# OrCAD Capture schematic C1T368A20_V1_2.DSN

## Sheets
1 EMMC: size A4; title: Telink; rev: V1.2; note: C1T368A20
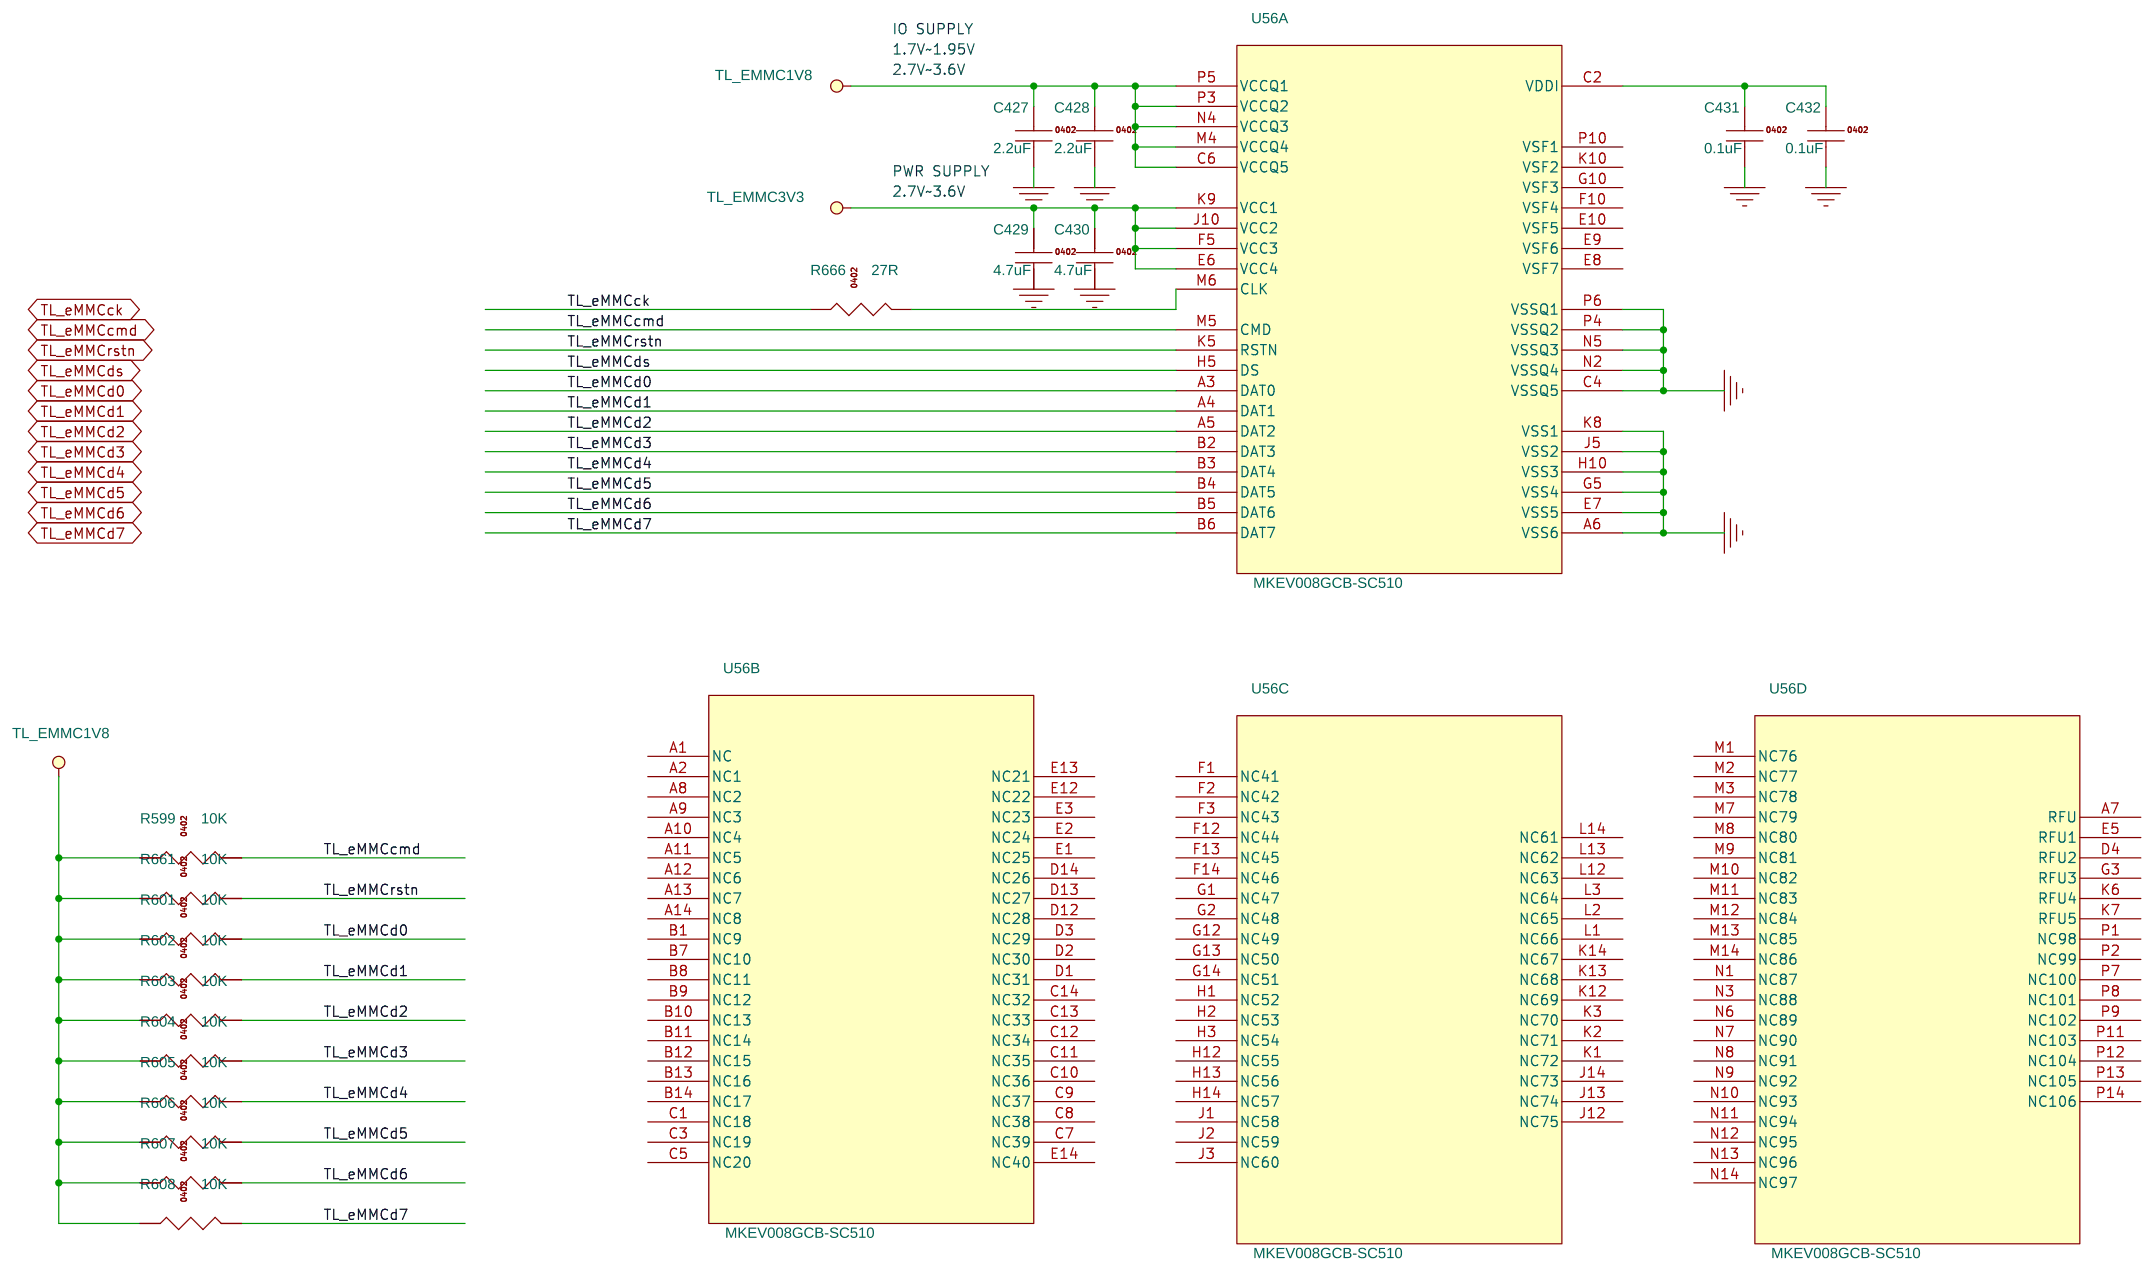
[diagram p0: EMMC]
2 001_Log
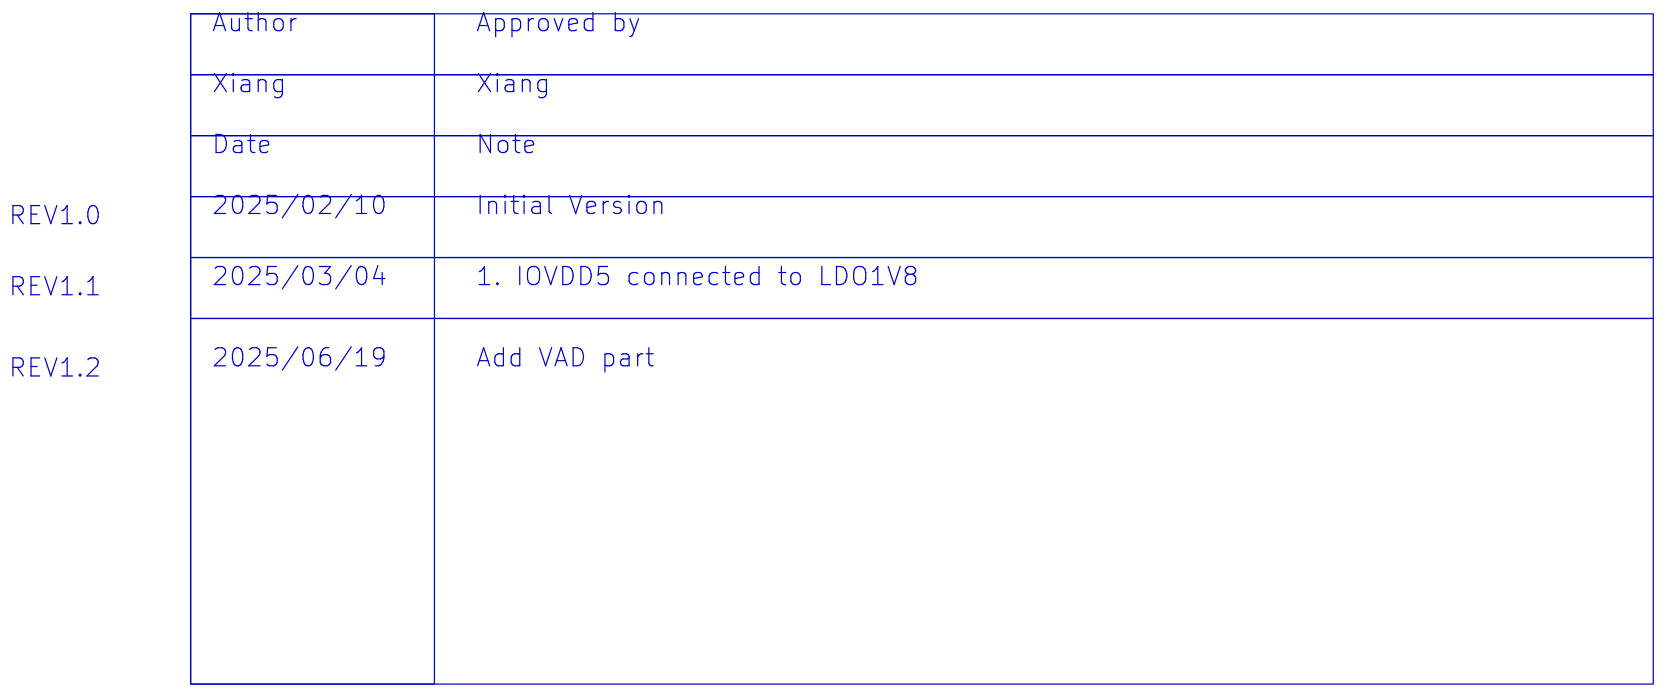
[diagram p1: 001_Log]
3 002_STR
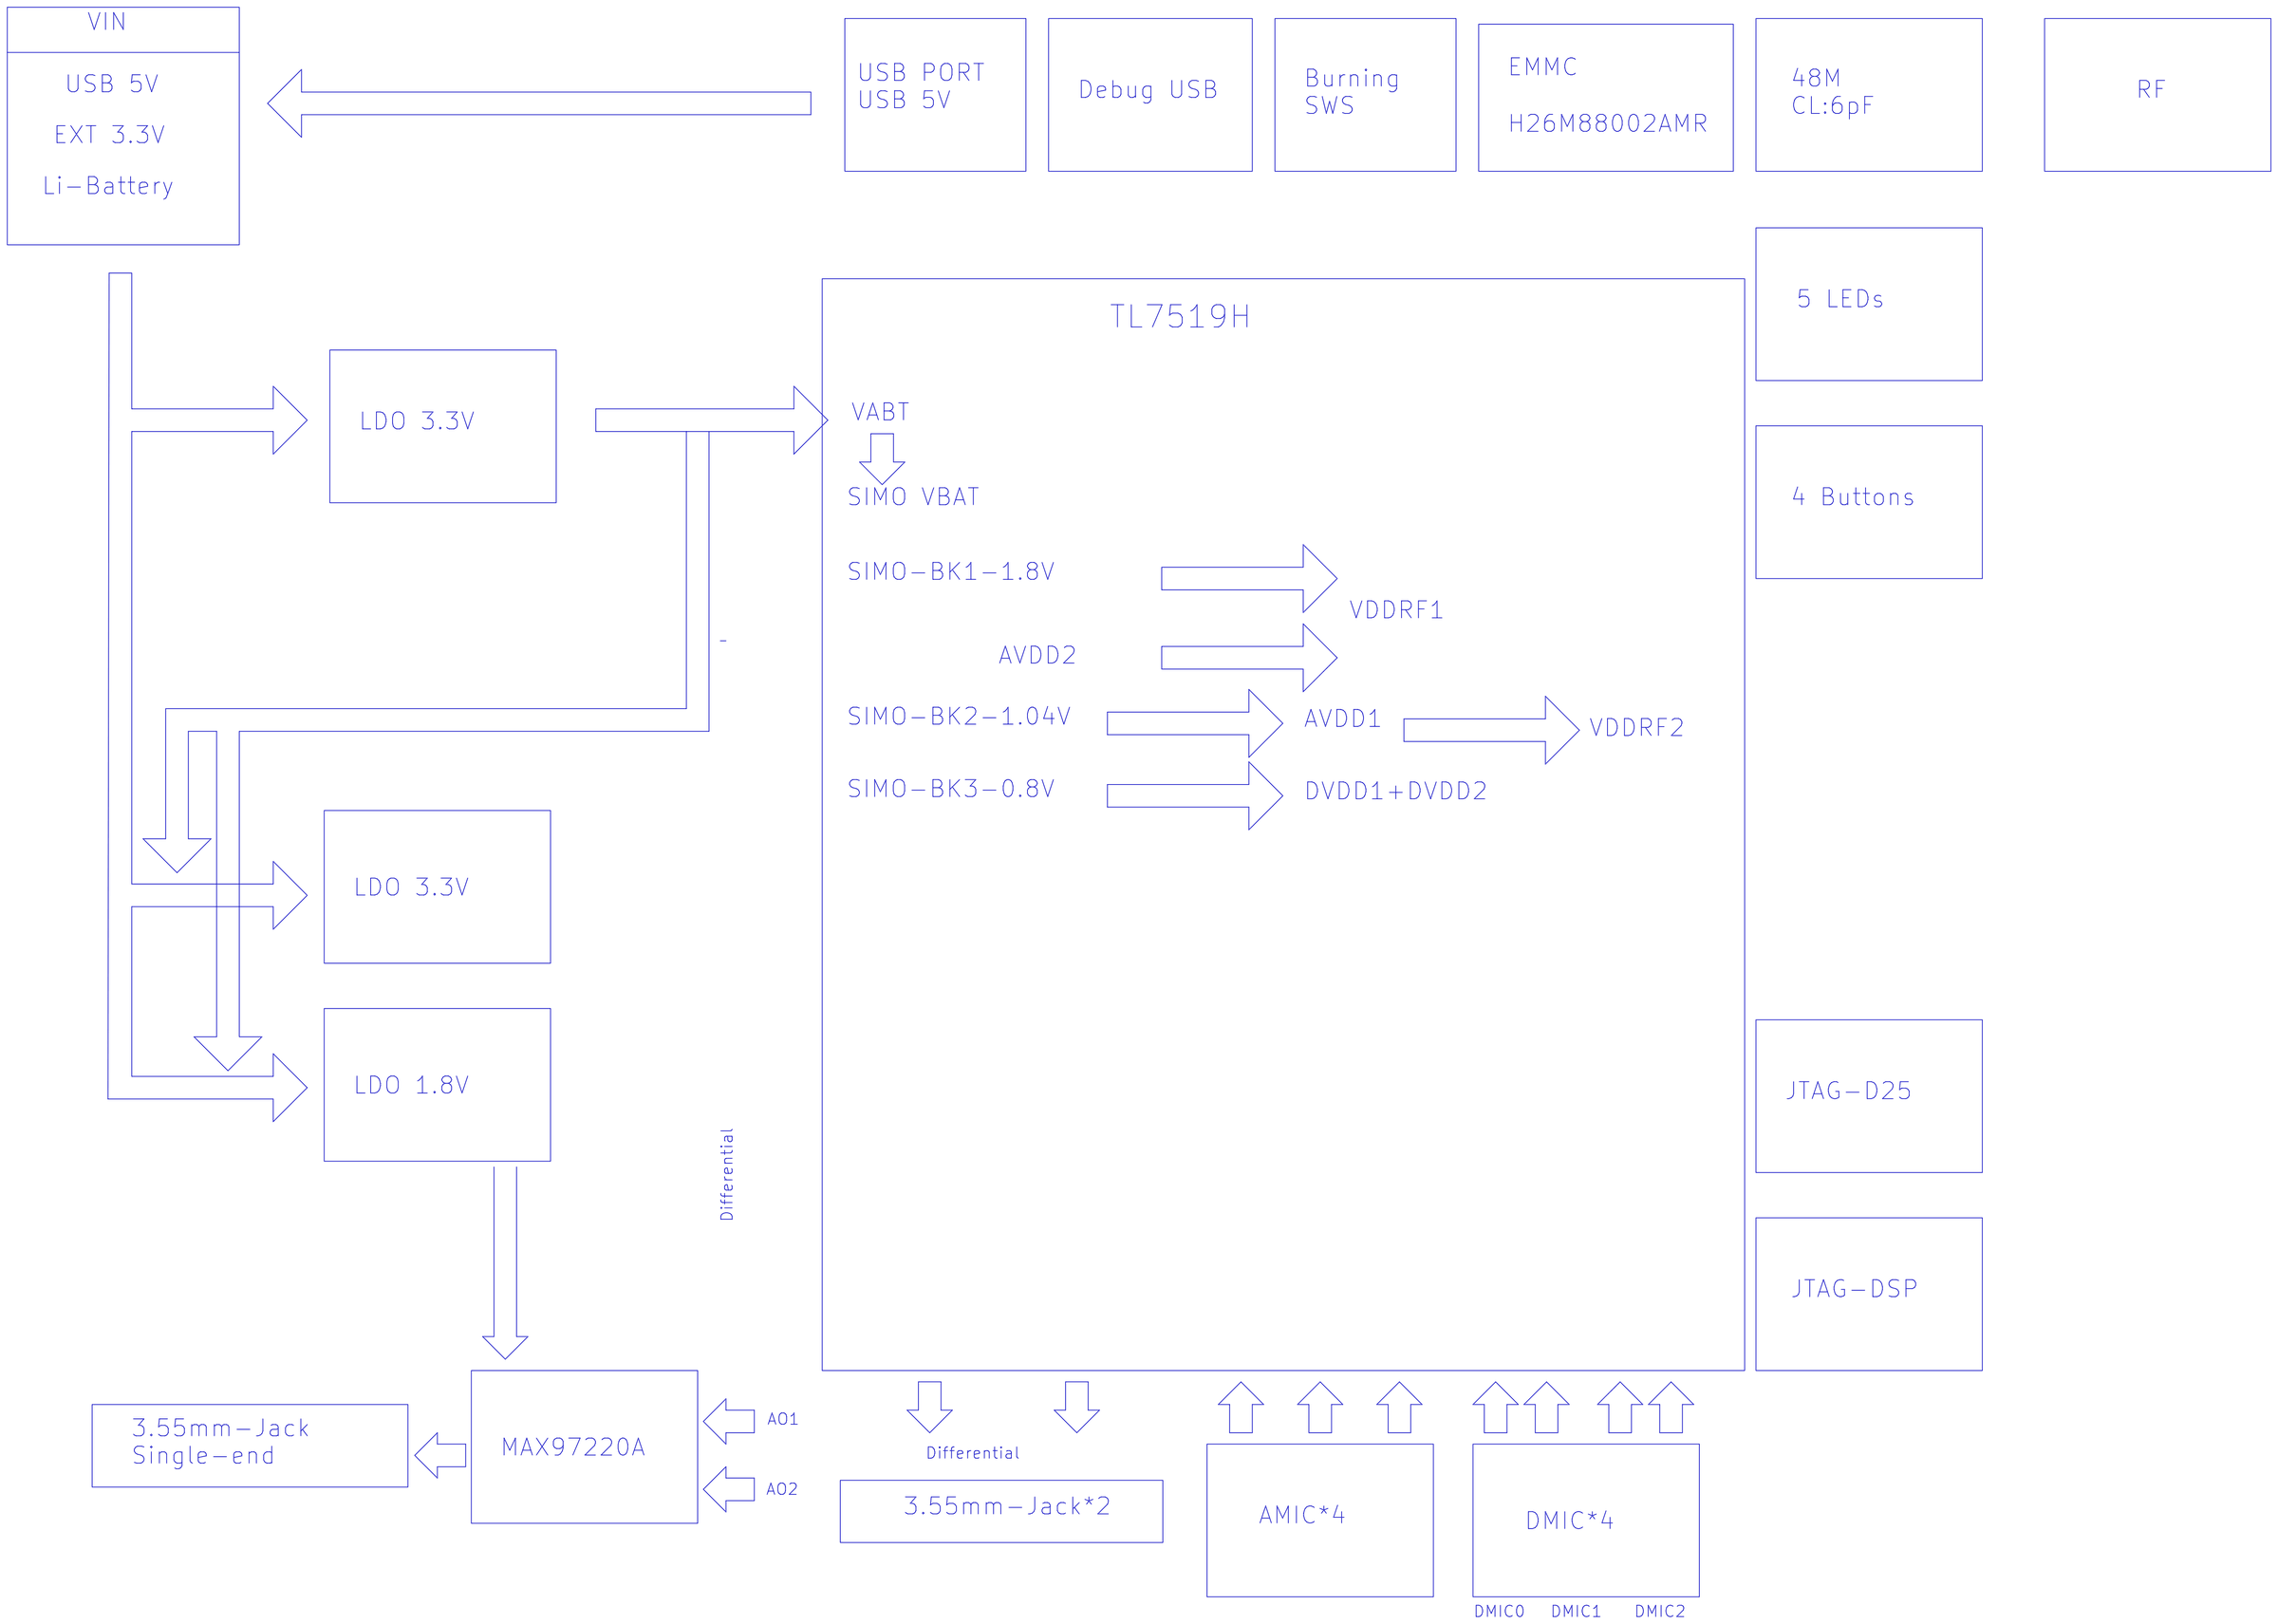
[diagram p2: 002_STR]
4 003_MAIN: size A4
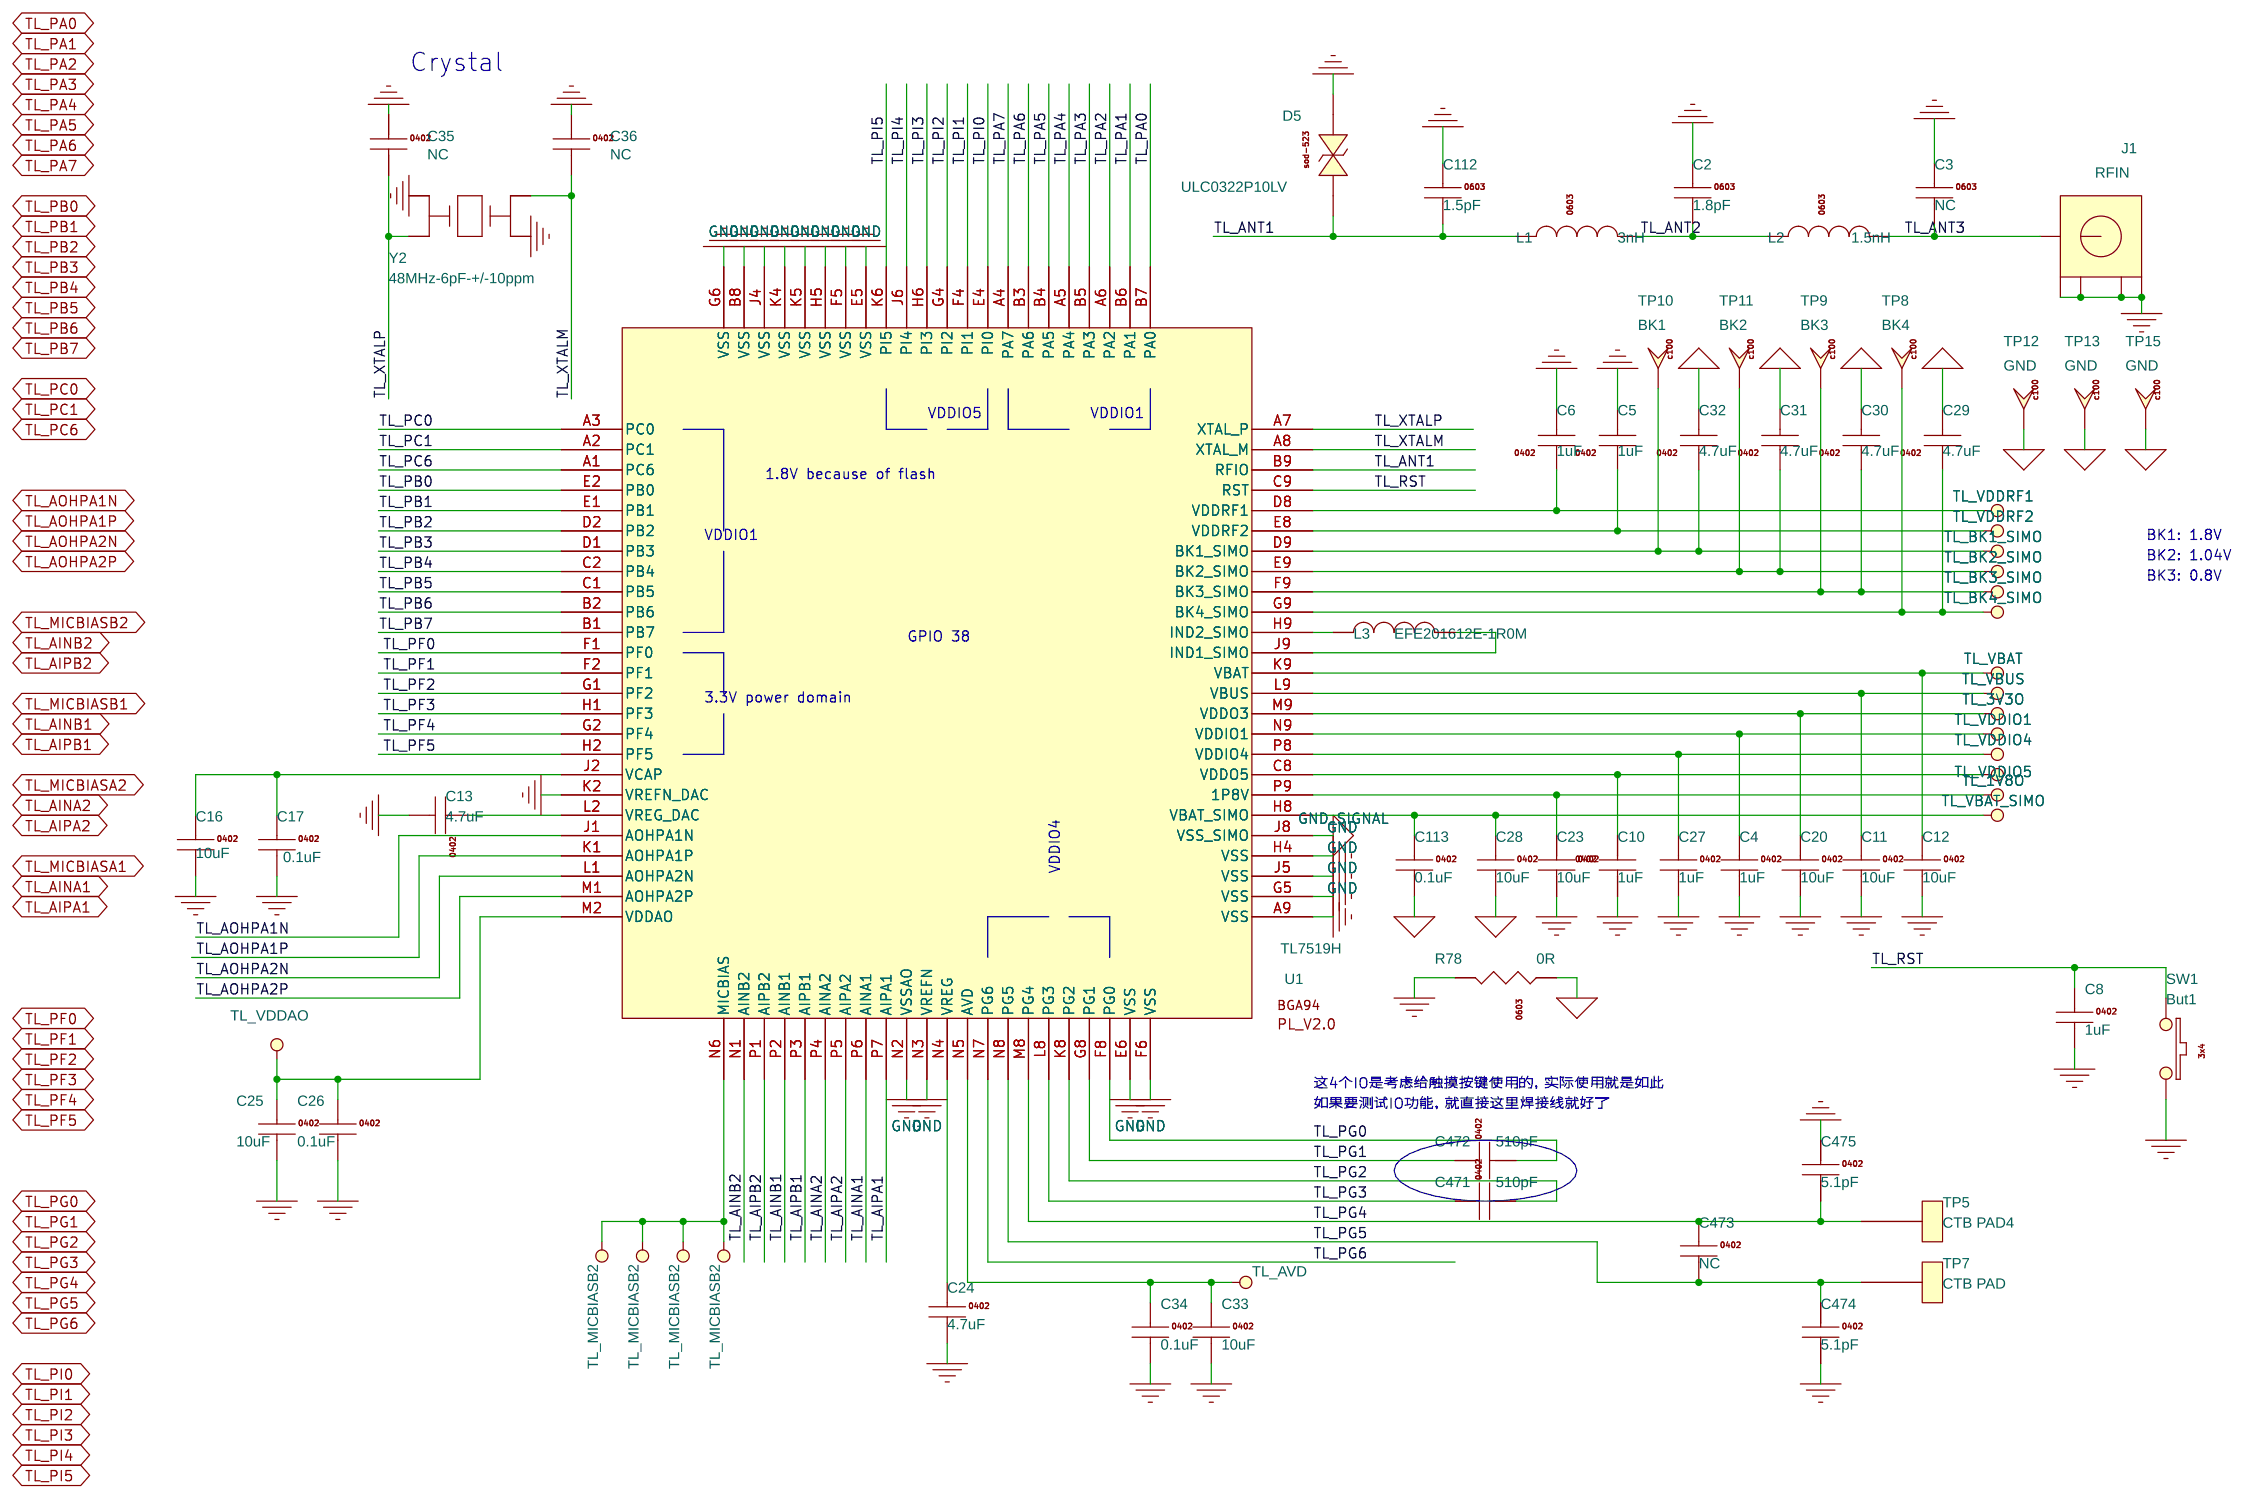
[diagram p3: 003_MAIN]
5 004_Interface: size A4
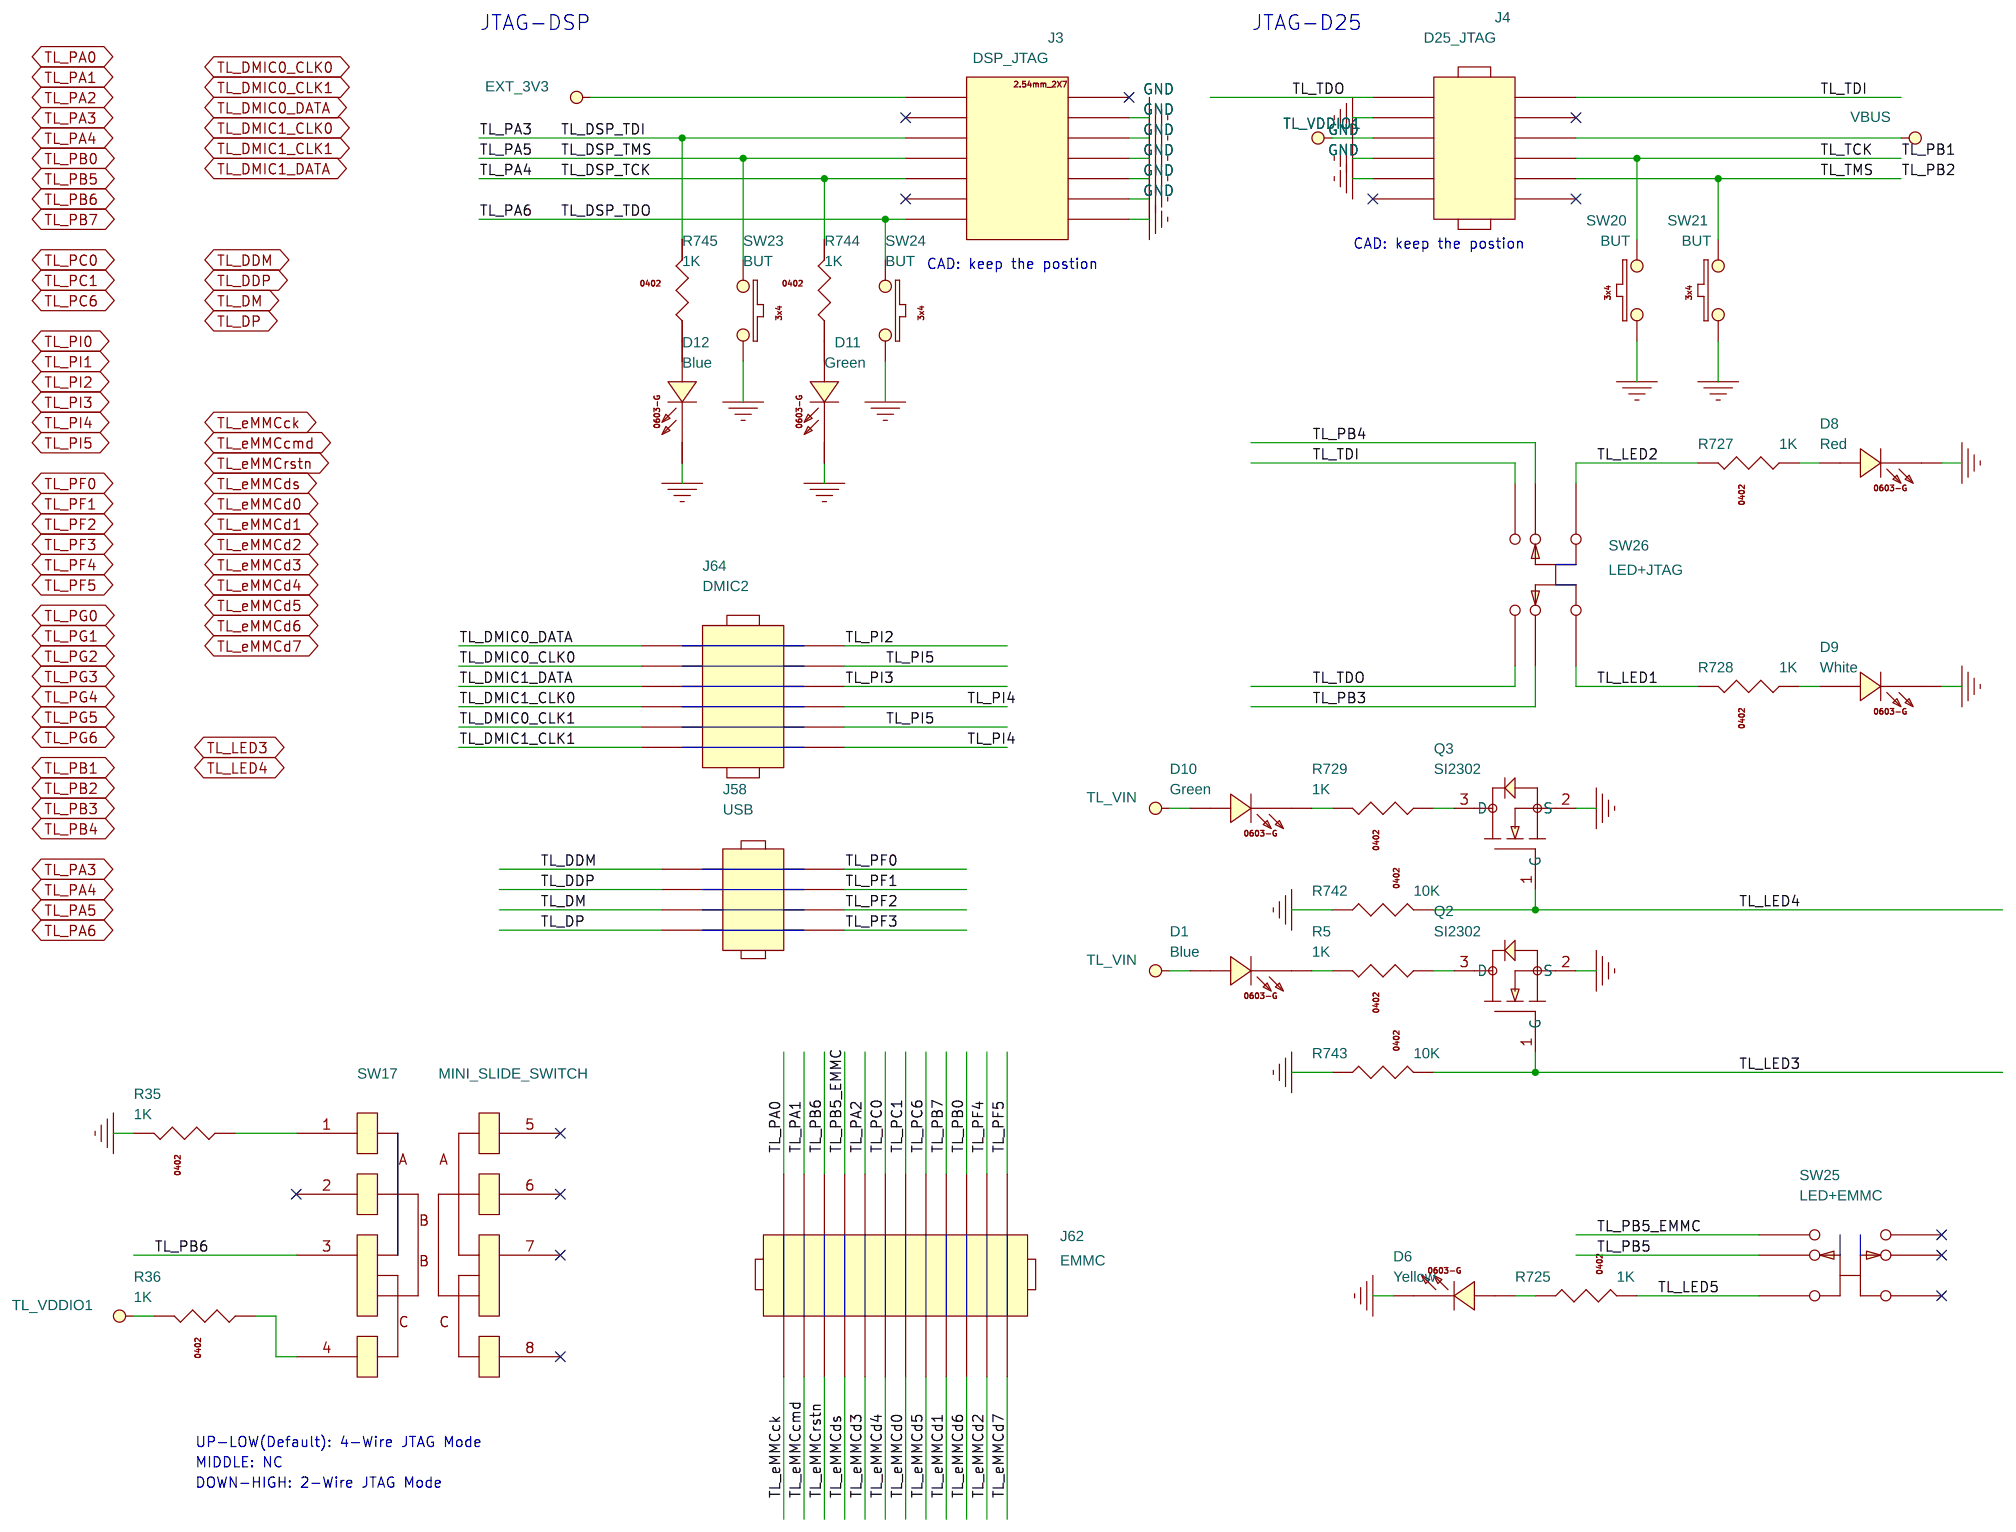
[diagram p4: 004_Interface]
6 005_AMIC: size A3
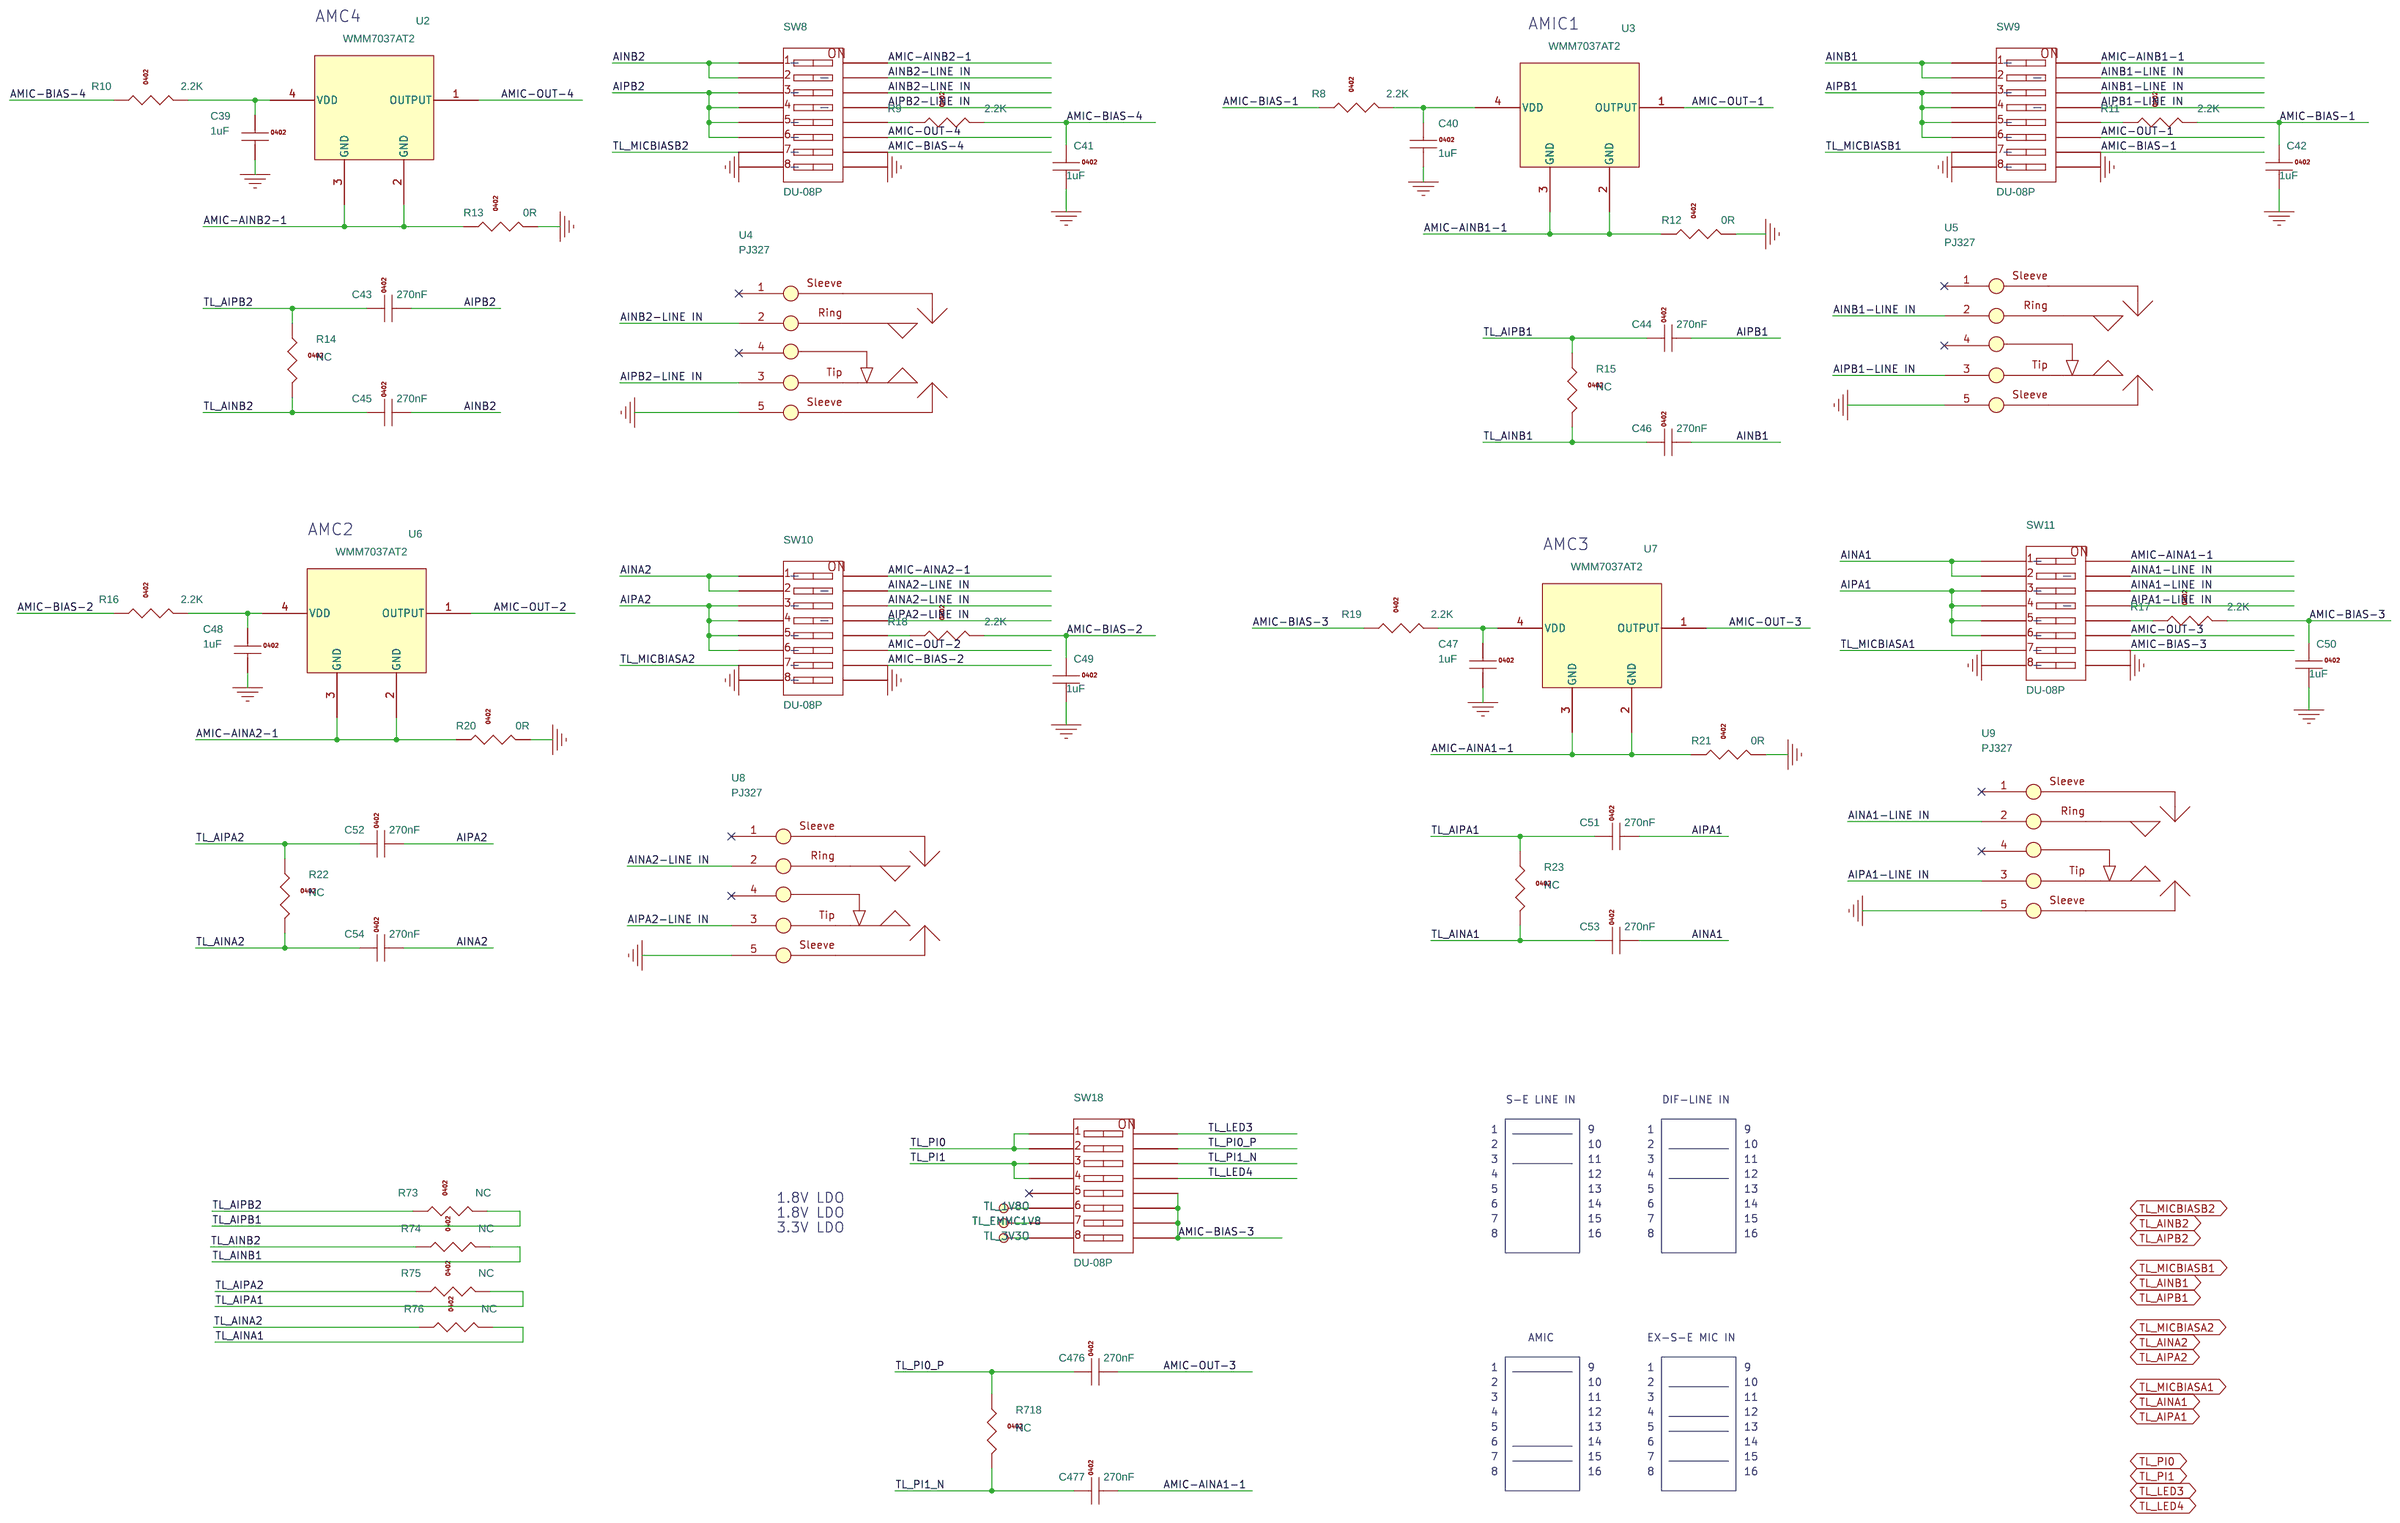
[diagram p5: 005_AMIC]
7 006_DMIC: size A4
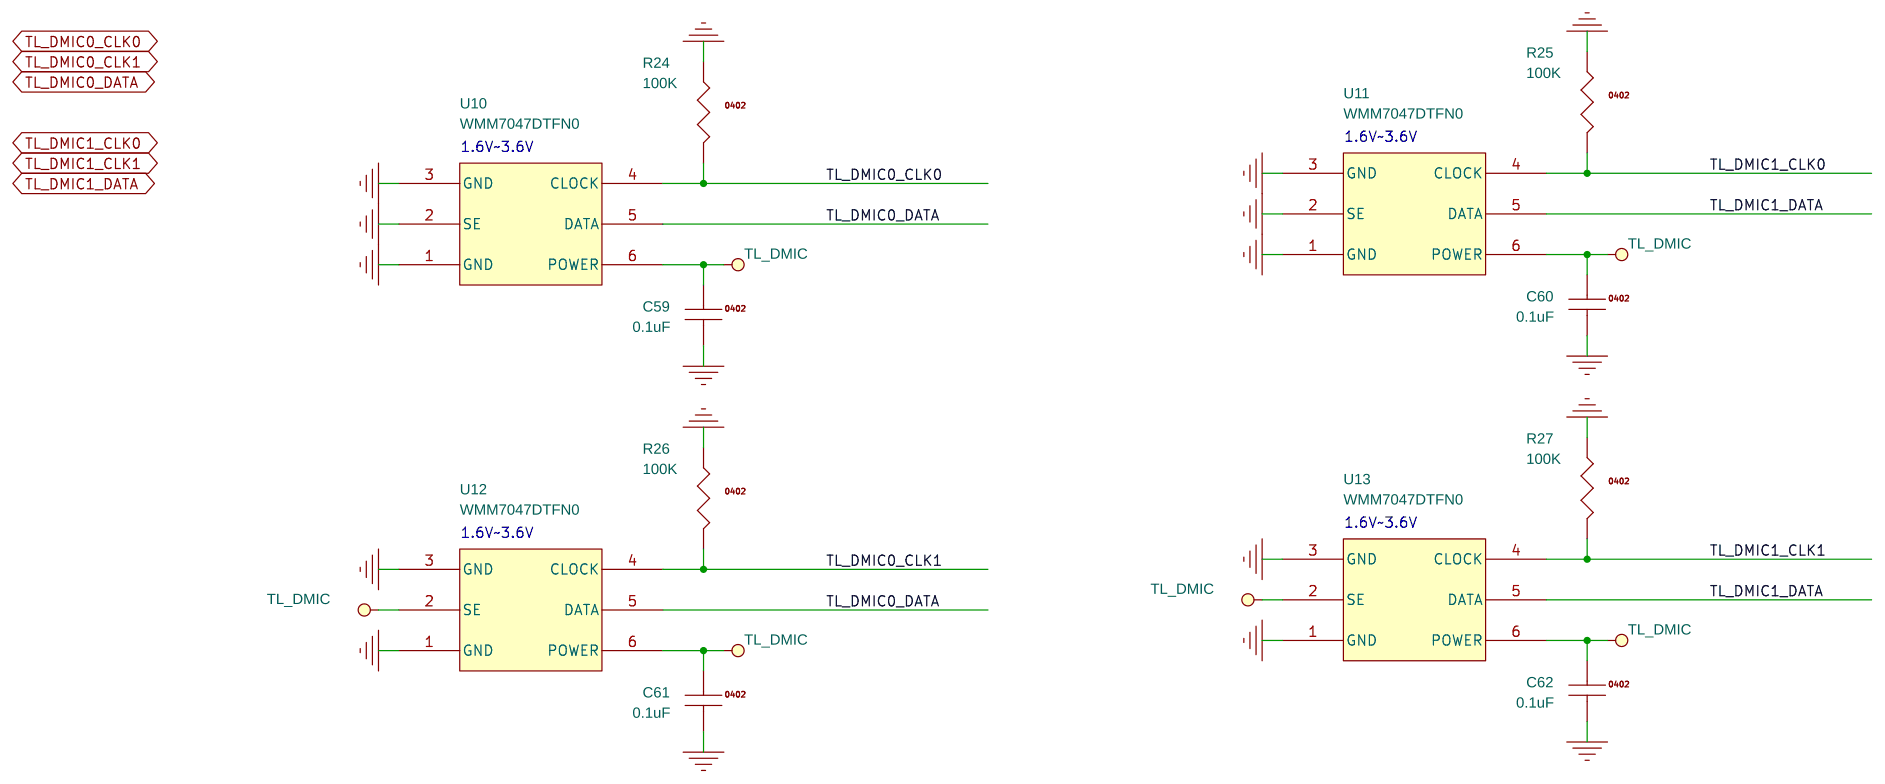
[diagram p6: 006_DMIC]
8 007_DAC Output: size A4
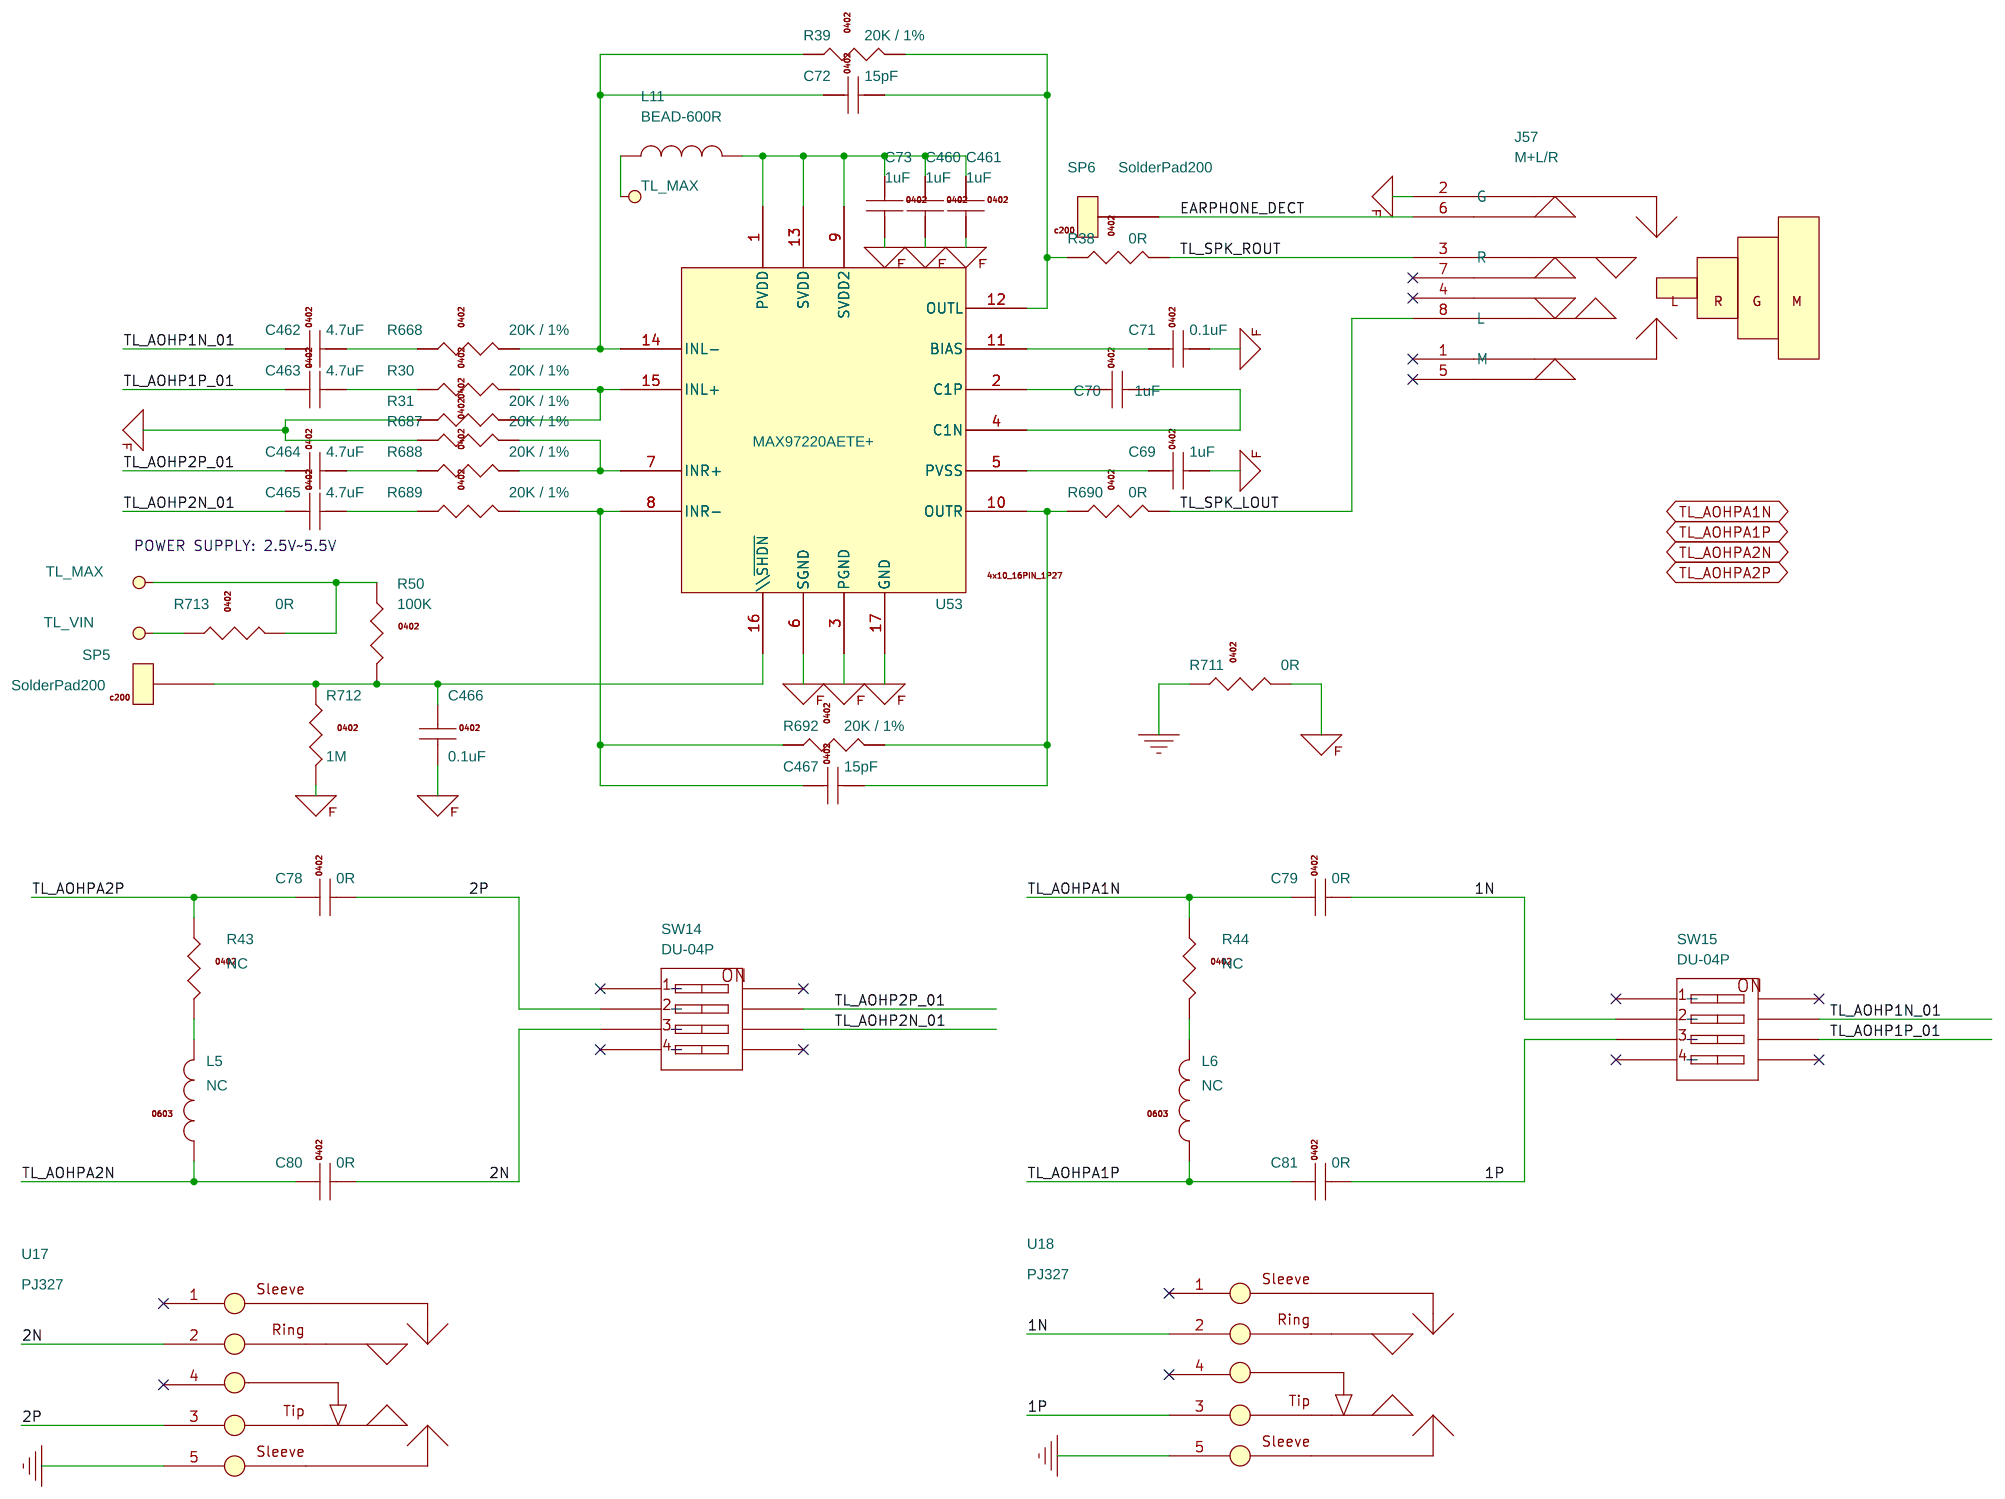
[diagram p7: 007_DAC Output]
9 009_PWR: size A4
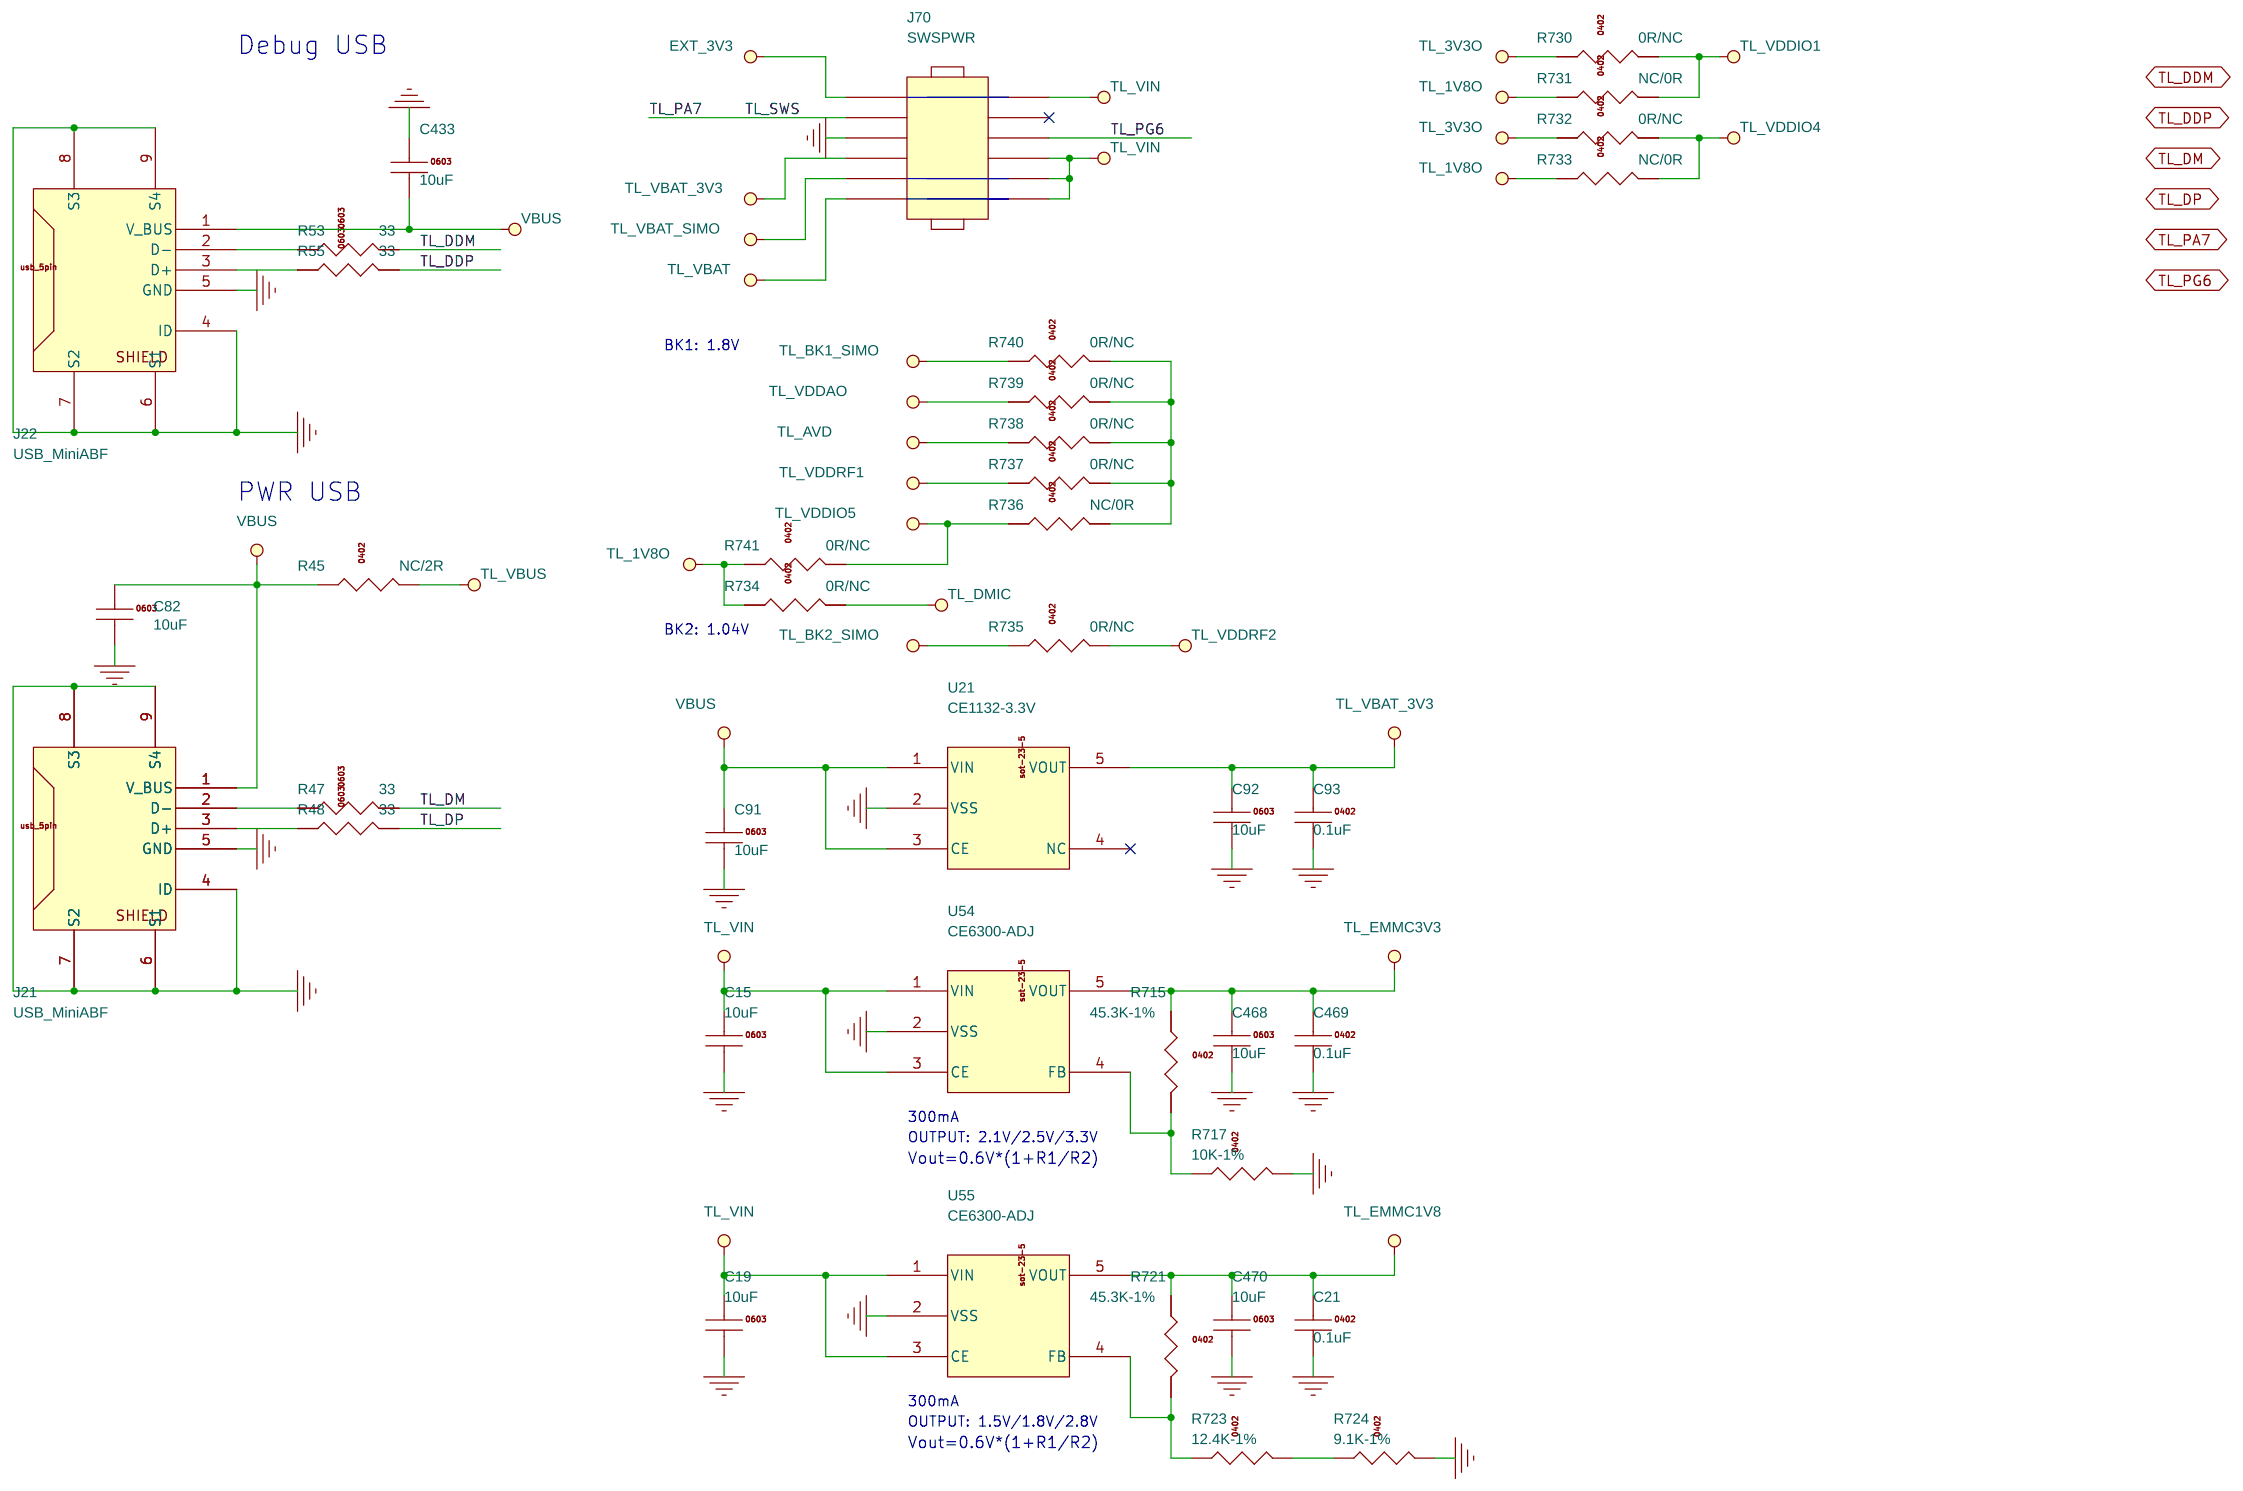
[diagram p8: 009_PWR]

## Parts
sheet 003_MAIN
C2  1.8pF  [0201]
C3  NC  [0201]
C4  1uF  [0402]
C5  1uF  [0402]
C6  1uF  [0402]
C8  1uF  [0402]
C10  1uF  [0402]
C11  10uF  [0402]
C12  10uF  [0402]
C13  4.7uF  [0402]
C16  10uF  [0402]
C17  0.1uF  [0402]
C20  10uF  [0402]
C23  10uF  [0402]
C24  4.7uF  [0402]
C25  10uF  [0402]
C26  0.1uF  [0402]
C27  1uF  [0402]
C28  10uF  [0402]
C29  4.7uF  [0402]
C30  4.7uF  [0402]
C31  4.7uF  [0402]
C32  4.7uF  [0402]
C33  10uF  [0402]
C34  0.1uF  [0402]
C35  NC  [0402]
C36  NC  [0402]
C112  1.5pF  [0201]
C113  0.1uF  [0402]
C471  510pF  [0402]
C472  510pF  [0402]
C473  NC  [0402]
C474  5.1pF  [0402]
C475  5.1pF  [0402]
D5  ULC0322P10LV  [0201]
J1  RFIN  [SMA-H]
L1  3nH  [0201]
L2  1.5nH  [0201]
L3  EFE201612E-1R0M  [1008L]
R78  0R  [0402]
SW1  But1  [butsmd2px4_00y3_00_nh]
TP5  CTB PAD4  [tp12mm]
TP7  CTB PAD  [tp12mm]
TP8  BK4  [TP100]
TP9  BK3  [TP100]
TP10  BK1  [TP100]
TP11  BK2  [TP100]
TP12  GND  [TP100]
TP13  GND  [TP100]
TP15  GND  [TP100]
U1  TL7519H  [bga_4x6_94pin_0p4]
Y2  48MHz-6pF-+/-10ppm  [OSCCC250X320X110]
sheet 004_Interface
D1  Blue  [0603-LED]
D6  Yellow  [0603-LED]
D8  Red  [0603-LED]
D9  White  [0603-LED]
D10  Green  [0603-LED]
D11  Green  [0603-LED]
D12  Blue  [0603-LED]
J3  DSP_JTAG  [smd254m-2x7_rx1_30y2_40]
J4  D25_JTAG  [smd254m-2x6_rx1_30y2_40]
J58  USB  [smd254m-2x4_rx1_30y2_40]
J62  EMMC  [smd254m-2x12_rx1_30y2_40]
J64  DMIC2  [smd254m-2x6_rx1_30y2_40]
Q2  SI2302  [mos_sot-23]
Q3  SI2302  [mos_sot-23]
R5  1K  [0402]
R35  1K  [0402]
R36  1K  [0402]
R725  1K  [0402]
R727  1K  [0402]
R728  1K  [0402]
R729  1K  [0402]
R742  10K  [0402]
R743  10K  [0402]
R744  1K  [0402]
R745  1K  [0402]
SW17  MINI_SLIDE_SWITCH  [SW-SMD-8PIN-12P95X3P5-2]
SW20  BUT  [butsmd2px4_00y3_00_nh]
SW21  BUT  [butsmd2px4_00y3_00_nh]
SW23  BUT  [butsmd2px4_00y3_00_nh]
SW24  BUT  [butsmd2px4_00y3_00_nh]
SW25  LED+EMMC  [SW-SMD-6PIN-9P1X3P5-2P5]
SW26  LED+JTAG  [SW-SMD-6PIN-9P1X3P5-2P5]
sheet 005_AMIC
C39  1uF  [0402]
C40  1uF  [0402]
C41  1uF  [0402]
C42  1uF  [0402]
C43  270nF  [0402]
C44  270nF  [0402]
C45  270nF  [0402]
C46  270nF  [0402]
C47  1uF  [0402]
C48  1uF  [0402]
C49  1uF  [0402]
C50  1uF  [0402]
C51  270nF  [0402]
C52  270nF  [0402]
C53  270nF  [0402]
C54  270nF  [0402]
C476  270nF  [0402]
C477  270nF  [0402]
R8  2.2K  [0402]
R9  2.2K  [0402]
R10  2.2K  [0402]
R11  2.2K  [0402]
R12  0R  [0402]
R13  0R  [0402]
R14  NC  [0402]
R15  NC  [0402]
R16  2.2K  [0402]
R17  2.2K  [0402]
R18  2.2K  [0402]
R19  2.2K  [0402]
R20  0R  [0402]
R21  0R  [0402]
R22  NC  [0402]
R23  NC  [0402]
R73  NC  [0402]
R74  NC  [0402]
R75  NC  [0402]
R76  NC  [0402]
R718  NC  [0402]
SW8  DU-08P  [EHS-JH_1p27_8x2]
SW9  DU-08P  [EHS-JH_1p27_8x2]
SW10  DU-08P  [EHS-JH_1p27_8x2]
SW11  DU-08P  [EHS-JH_1p27_8x2]
SW18  DU-08P  [EHS-JH_1p27_8x2]
U2  WMM7037AT2  [ga_bfa423_a83]
U3  WMM7037AT2  [ga_bfa423_a83]
U4  PJ327  [PJ-327]
U5  PJ327  [PJ-327]
U6  WMM7037AT2  [ga_bfa423_a83]
U7  WMM7037AT2  [ga_bfa423_a83]
U8  PJ327  [PJ-327]
U9  PJ327  [PJ-327]
sheet 006_DMIC
C59  0.1uF  [0402]
C60  0.1uF  [0402]
C61  0.1uF  [0402]
C62  0.1uF  [0402]
R24  100K  [0402]
R25  100K  [0402]
R26  100K  [0402]
R27  100K  [0402]
U10  WMM7047DTFN0  [DMIC_SPM0423HM4H-WB]
U11  WMM7047DTFN0  [DMIC_SPM0423HM4H-WB]
U12  WMM7047DTFN0  [DMIC_SPM0423HM4H-WB]
U13  WMM7047DTFN0  [DMIC_SPM0423HM4H-WB]
sheet 007_DAC Output
C69  1uF  [0402]
C70  1uF  [0402]
C71  0.1uF  [0402]
C72  15pF  [0402]
C73  1uF  [0402]
C78  0R  [0402]
C79  0R  [0402]
C80  0R  [0402]
C81  0R  [0402]
C460  1uF  [0402]
C461  1uF  [0402]
C462  4.7uF  [0402]
C463  4.7uF  [0402]
C464  4.7uF  [0402]
C465  4.7uF  [0402]
C466  0.1uF  [0402]
C467  15pF  [0402]
J57  M+L/R  [PJ-382-8P]
L5  NC  [1008L]
L6  NC  [1008L]
L11  BEAD-600R  [0603L]
R30  20K / 1%  [0402]
R31  20K / 1%  [0402]
R38  0R  [0402]
R39  20K / 1%  [0402]
R43  NC  [0402]
R44  NC  [0402]
R50  100K  [0402]
R668  20K / 1%  [0402]
R687  20K / 1%  [0402]
R688  20K / 1%  [0402]
R689  20K / 1%  [0402]
R690  0R  [0402]
R692  20K / 1%  [0402]
R711  0R  [0402]
R712  1M  [0402]
R713  0R  [0402]
SP5  SolderPad200  [TP200]
SP6  SolderPad200  [TP200]
SW14  DU-04P  [EHS-JH_1p27_4x2]
SW15  DU-04P  [EHS-JH_1p27_4x2]
U17  PJ327  [PJ-327]
U18  PJ327  [PJ-327]
U53  MAX97220AETE+  [qfn_3x3_16pin_0p5_1p70x1p70]
sheet 009_PWR
C15  10uF  [0603C]
C19  10uF  [0603C]
C21  0.1uF  [0402]
C82  10uF  [0603C]
C91  10uF  [0603C]
C92  10uF  [0603C]
C93  0.1uF  [0402]
C433  10uF  [0603C]
C468  10uF  [0603C]
C469  0.1uF  [0402]
C470  10uF  [0603C]
J21  USB_MiniABF  [USB-MINI-F5]
J22  USB_MiniABF  [USB-MINI-F5]
J70  SWSPWR  [smd254m-2x6_rx1_30y2_40]
R45  NC/2R  [0402]
R47  33  [0402R]
R48  33  [0402R]
R53  33  [0402R]
R55  33  [0402R]
R715  45.3K-1%  [0402]
R717  10K-1%  [0402]
R721  45.3K-1%  [0402]
R723  12.4K-1%  [0402]
R724  9.1K-1%  [0402]
R730  0R/NC  [0402]
R731  NC/0R  [0402]
R732  0R/NC  [0402]
R733  NC/0R  [0402]
R734  0R/NC  [0402]
R735  0R/NC  [0402]
R736  NC/0R  [0402]
R737  0R/NC  [0402]
R738  0R/NC  [0402]
R739  0R/NC  [0402]
R740  0R/NC  [0402]
R741  0R/NC  [0402]
U21  CE1132-3.3V  [sot-23-5]
U54  CE6300-ADJ  [sot-23-5]
U55  CE6300-ADJ  [sot-23-5]
sheet EMMC
C427  2.2uF  [0402]
C428  2.2uF  [0402]
C429  4.7uF  [0402]
C430  4.7uF  [0402]
C431  0.1uF  [0402]
C432  0.1uF  [0402]
R599  10K  [0402]
R601  10K  [0402]
R602  10K  [0402]
R603  10K  [0402]
R604  10K  [0402]
R605  10K  [0402]
R606  10K  [0402]
R607  10K  [0402]
R608  10K  [0402]
R661  10K  [0402]
R666  27R  [0402]
U56  MKEV008GCB-SC510  [FBGA153]  (sections A,B,C,D)

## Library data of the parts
C2 C3 C112 = C1608_NC
C4-C6 C8 C10-C13 C16 C17 C20 C21 C23-C34 C39-C54 C59-C62 C69-C73 C93 C113 C427-C432 C460-C467 C469 C471-C477 = C1005X5R1C104K
C35 C36 = C1005_NC
D5 = ESD5B5_0.0ST1G
J1 = SMA_JACK_2: PART: RF
L1 L2 L5 L6 = MLK1608_000R
L3 L11 = IND
R78 = RS0603K102JT
SW1 SW20 SW21 SW23 SW24 = SW2PIN_3x4
TP5 TP7 = TEST_POINT
TP8-TP13 TP15 = TestPad100
U1 = TL7519H-BGA94
Y2 = CRYSTAL4_SM_0
D1 D6 D8-D12 = 0603D_Green
J3 = CON_0.54mm_2x7
J4 J64 J70 = HEADER_6X2
J58 = HEADER_4X2
J62 = HEADER_12X2
Q2 Q3 = NMOS_SI2302
R5 R715 R717 R721 R723-R725 R727-R729 R744 R745 = RS0402K102JT
R35 R36 R742 R743 = RS0402K103JT
SW17 = MINI_SLIDE_SWITCH
SW25 SW26 = SW_SL_DPDT
R8-R27 R30 R31 R38 R39 R43-R45 R50 R73-R76 R668 R687-R690 R692 R711-R713 R718 R730-R741 = RS0402K104JT
SW8-SW11 SW18 = EHS-JH-108
U2 U3 U6 U7 = MULPS4CX-RM5_0
U4 U5 U8 U9 U17 U18 = PJ327
U10-U13 = LD1117_SO_0
C78-C81 = C1005X5R1C105K
J57 = PJ327_2
SP5 SP6 = SolderPad200
SW14 SW15 = EHS-JH-104
U53 = TLSR8368EP16_1
C15 C19 C82 C91 C92 C433 C468 C470 = C1608X5R0J106M
J21 J22 = USB_MiniABF_5pin
R47 R48 R53 R55 = RS0603K330JT
U21 = XC6219_5.3V_SOT-23-5
U54 U55 = XC6219_1.3V_SOT-23-5
R599 R601-R608 R661 R666 = RS0402K330JT
U56 = H26M88002AMR

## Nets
GND: C2.1 C3.1 C4.2 C5.2 C6.2 C8.2 C10.2 C11.2 C12.2 C13.2 C15.2 C16.2 C17.2 C19.2 C20.2 C21.2 C23.2 C24.2 C25.2 C26.2 C27.2 C33.2 C34.2 C35.1 C36.1 C39.2 C40.2 C41.2 C42.2 C47.2 C48.2 C49.2 C50.2 C59.2 C60.2 C61.2 C62.2 C82.2 C91.2 C92.2 C93.2 C112.1 C427.2 C428.2 C429.2 C430.2 C431.2 C432.2 C433.1 C468.2 C469.2 C470.2 C474.2 C475.1 D5.2 D6.C(CATHODE) D8.C(CATHODE) D9.C(CATHODE) D11.C(CATHODE) D12.C(CATHODE) J1.2 J1.3 J1.4 J1.5 J3.3 J3.5 J3.7 J3.9 J3.11 J3.13 J4.3 J4.5 J4.9 J21.4(ID) J21.5(GND) J21.6(S1) J21.7(S2) J21.8(S3) J21.9(S4) J22.4(ID) J22.5(GND) J22.6(S1) J22.7(S2) J22.8(S3) J22.9(S4) J70.6 Q2.2(S) Q3.2(S) R12.2 R13.2 R20.2 R21.2 R24.1 R25.1 R26.1 R27.1 R35.1 R78.2 R711.1 R717.2 R724.2 R742.2 R743.2 SW1.2 SW8.8 SW8.16 SW9.8 SW9.16 SW10.8 SW10.16 SW11.8 SW11.16 SW20.2 SW21.2 SW23.2 SW24.2 U1.A9(VSS) U1.B8(VSS) U1.E5(VSS) U1.E6(VSS) U1.F5(VSS) U1.F6(VSS) U1.G5(VSS) U1.G6(VSS) U1.H4(VSS) U1.H5(VSS) U1.J4(VSS) U1.J5(VSS) U1.K2(VREFN_DAC) U1.K4(VSS) U1.K5(VSS) U1.N2(VSSAO) U1.N3(VREFN) U4.5 U5.5 U8.5 U9.5 U10.1(GND) U10.2(SE) U10.3(GND) U11.1(GND) U11.2(SE) U11.3(GND) U12.1(GND) U12.3(GND) U13.1(GND) U13.3(GND) U17.5 U18.5 U21.2(VSS) U54.2(VSS) U55.2(VSS) U56.A6(VSS6) U56.C4(VSSQ5) U56.E7(VSS5) U56.G5(VSS4) U56.H10(VSS3) U56.J5(VSS2) U56.K8(VSS1) U56.N2(VSSQ4) U56.N5(VSSQ3) U56.P4(VSSQ2) U56.P6(VSSQ1) Y2.2 Y2.4
GND_FIELD SIGNAL: C69.2 C71.2 C73.2 C460.2 C461.2 C466.2 J57.2(G) R31.1 R687.1 R711.2 R712.2 U53.3(PGND) U53.6(SGND) U53.17(GND)
GND_SIGNAL: C28.2 C29.2 C30.2 C31.2 C32.2 C113.2 R78.1 TP12.1(TP) TP13.1(TP) TP15.1(TP) U1.J8(VSS_SIMO)
VBUS: C82.1 C91.1 C433.2 J4.8 J21.1(V_BUS) J22.1(V_BUS) R45.1 U21.1(VIN) U21.3(CE)
1N: C79.2 SW15.2 U18.2
1P: C81.2 SW15.3 U18.3
2N: C80.2 SW14.3 U17.2
2P: C78.2 SW14.2 U17.3
AINA1: C53.2 SW11.1 SW11.2
AINA1-LINE IN: SW11.10 SW11.11 U9.2
AINA2: C54.2 SW10.1 SW10.2
AINA2-LINE IN: SW10.10 SW10.11 U8.2
AINB1: C46.2 SW9.1 SW9.2
AINB1-LINE IN: SW9.10 SW9.11 U5.2
AINB2: C45.2 SW8.1 SW8.2
AINB2-LINE IN: SW8.10 SW8.11 U4.2
AIPA1: C51.2 SW11.3 SW11.4 SW11.5 SW11.6
AIPA1-LINE IN: SW11.12 U9.3
AIPA2: C52.2 SW10.3 SW10.4 SW10.5 SW10.6
AIPA2-LINE IN: SW10.12 U8.3
AIPB1: C44.2 SW9.3 SW9.4 SW9.5 SW9.6
AIPB1-LINE IN: SW9.12 U5.3
AIPB2: C43.2 SW8.3 SW8.4 SW8.5 SW8.6
AIPB2-LINE IN: SW8.12 U4.3
AMIC-AINA1-1: C477.2 R21.1 SW11.9 U7.2(GND) U7.3(GND)
AMIC-AINA2-1: R20.1 SW10.9 U6.2(GND) U6.3(GND)
AMIC-AINB1-1: R12.1 SW9.9 U3.2(GND) U3.3(GND)
AMIC-AINB2-1: R13.1 SW8.9 U2.2(GND) U2.3(GND)
AMIC-BIAS-1: C42.1 R8.1 R11.2 SW9.15
AMIC-BIAS-2: C49.1 R16.1 R18.2 SW10.15
AMIC-BIAS-3: C50.1 R17.2 R19.1 SW11.15 SW18.13 SW18.14 SW18.15 SW18.16
AMIC-BIAS-4: C41.1 R9.2 R10.1 SW8.15
AMIC-OUT-1: SW9.14 U3.1(OUTPUT)
AMIC-OUT-2: SW10.14 U6.1(OUTPUT)
AMIC-OUT-3: C476.2 SW11.14 U7.1(OUTPUT)
AMIC-OUT-4: SW8.14 U2.1(OUTPUT)
EARPHONE_DECT: J57.6 SP6.1
EXT_3V3: J3.2 J70.2
TL_1V8O: C23.1 R731.1 R733.1 R734.1 R741.1 SW18.6 U1.P9(1P8V)
TL_3V3O: C20.1 R730.1 R732.1 SW18.8 U1.M9(VDDO3)
TL_AINA1: U1.P6(AINA1)
TL_AINA1 (page 005_AMIC): C53.1 R23.2 R76.2
TL_AINA2: U1.P4(AINA2)
TL_AINA2 (page 005_AMIC): C54.1 R22.2 R76.1
TL_AINB1: U1.P2(AINB1)
TL_AINB1 (page 005_AMIC): C46.1 R15.2 R74.2
TL_AINB2: U1.N1(AINB2)
TL_AINB2 (page 005_AMIC): C45.1 R14.2 R74.1
TL_AIPA1: U1.P7(AIPA1)
TL_AIPA1 (page 005_AMIC): C51.1 R23.1 R75.2
TL_AIPA2: U1.P5(AIPA2)
TL_AIPA2 (page 005_AMIC): C52.1 R22.1 R75.1
TL_AIPB1: U1.P3(AIPB1)
TL_AIPB1 (page 005_AMIC): C44.1 R15.1 R73.2
TL_AIPB2: U1.P1(AIPB2)
TL_AIPB2 (page 005_AMIC): C43.1 R14.1 R73.1
TL_ANT1: C112.2 D5.1 L1.1 U1.B9(RFIO)
TL_ANT2: C2.2 L1.2 L2.1
TL_ANT3: C3.2 J1.1 L2.2
TL_AOHP1N_01: C462.1 SW15.6
TL_AOHP1P_01: C463.1 SW15.7
TL_AOHP2N_01: C465.1 SW14.7
TL_AOHP2P_01: C464.1 SW14.6
TL_AOHPA1N: U1.J1(AOHPA1N)
TL_AOHPA1N (page 007_DAC Output): C79.1 R44.1
TL_AOHPA1P: U1.K1(AOHPA1P)
TL_AOHPA1P (page 007_DAC Output): C81.1 L6.1
TL_AOHPA2N: U1.L1(AOHPA2N)
TL_AOHPA2N (page 007_DAC Output): C80.1 L5.1
TL_AOHPA2P: U1.M1(AOHPA2P)
TL_AOHPA2P (page 007_DAC Output): C78.1 R43.1
TL_AVD: C33.1 C34.1 R738.1 U1.N5(AVD)
TL_BK1_SIMO: C32.1 R740.1 TP10.1(TP) U1.D9(BK1_SIMO)
TL_BK2_SIMO: C31.1 R735.1 TP11.1(TP) U1.E9(BK2_SIMO)
TL_BK3_SIMO: C30.1 TP9.1(TP) U1.F9(BK3_SIMO)
TL_BK4_SIMO: C29.1 TP8.1(TP) U1.G9(BK4_SIMO)
TL_DDM: J58.2
TL_DDM (page 009_PWR): R53.2
TL_DDP: J58.4
TL_DDP (page 009_PWR): R55.2
TL_DM: J58.6
TL_DM (page 009_PWR): R47.2
TL_DMIC: C59.1 C60.1 C61.1 C62.1 R734.2 U10.6(POWER) U11.6(POWER) U12.2(SE) U12.6(POWER) U13.2(SE) U13.6(POWER)
TL_DMIC0_CLK0: J64.4
TL_DMIC0_CLK0 (page 006_DMIC): R24.2 U10.4(CLOCK)
TL_DMIC0_CLK1: J64.10
TL_DMIC0_CLK1 (page 006_DMIC): R26.2 U12.4(CLOCK)
TL_DMIC0_DATA: J64.2
TL_DMIC0_DATA (page 006_DMIC): U10.5(DATA) U12.5(DATA)
TL_DMIC1_CLK0: J64.8
TL_DMIC1_CLK0 (page 006_DMIC): R25.2 U11.4(CLOCK)
TL_DMIC1_CLK1: J64.12
TL_DMIC1_CLK1 (page 006_DMIC): R27.2 U13.4(CLOCK)
TL_DMIC1_DATA: J64.6
TL_DMIC1_DATA (page 006_DMIC): U11.5(DATA) U13.5(DATA)
TL_DP: J58.8
TL_DP (page 009_PWR): R48.2
TL_eMMC1V8: C21.1 C427.1 C428.1 C470.1 R599.1 R601.1 R602.1 R603.1 R604.1 R605.1 R606.1 R607.1 R608.1 R661.1 R721.1 SW18.7 U55.5(VOUT) U56.C6(VCCQ5) U56.M4(VCCQ4) U56.N4(VCCQ3) U56.P3(VCCQ2) U56.P5(VCCQ1)
TL_eMMC3V3: C429.1 C430.1 C468.1 C469.1 R715.1 U54.5(VOUT) U56.E6(VCC4) U56.F5(VCC3) U56.J10(VCC2) U56.K9(VCC1)
TL_eMMCck: J62.2
TL_eMMCck (page 008-EMMC): R666.1
TL_eMMCcmd: J62.4
TL_eMMCcmd (page 008-EMMC): R599.2 U56.M5(CMD)
TL_eMMCd0: J62.14
TL_eMMCd0 (page 008-EMMC): R601.2 U56.A3(DAT0)
TL_eMMCd1: J62.18
TL_eMMCd1 (page 008-EMMC): R602.2 U56.A4(DAT1)
TL_eMMCd2: J62.22
TL_eMMCd2 (page 008-EMMC): R603.2 U56.A5(DAT2)
TL_eMMCd3: J62.10
TL_eMMCd3 (page 008-EMMC): R604.2 U56.B2(DAT3)
TL_eMMCd4: J62.12
TL_eMMCd4 (page 008-EMMC): R605.2 U56.B3(DAT4)
TL_eMMCd5: J62.16
TL_eMMCd5 (page 008-EMMC): R606.2 U56.B4(DAT5)
TL_eMMCd6: J62.20
TL_eMMCd6 (page 008-EMMC): R607.2 U56.B5(DAT6)
TL_eMMCd7: J62.24
TL_eMMCd7 (page 008-EMMC): R608.2 U56.B6(DAT7)
TL_eMMCds: J62.8
TL_eMMCds (page 008-EMMC): U56.H5(DS)
TL_eMMCrstn: J62.6
TL_eMMCrstn (page 008-EMMC): R661.2 U56.K5(RSTN)
TL_LED1: R728.1 SW26.6
TL_LED2: R727.1 SW26.1
TL_LED3: Q2.1(G) R743.1
TL_LED3 (page 005_AMIC): SW18.9
TL_LED4: Q3.1(G) R742.1
TL_LED4 (page 005_AMIC): SW18.12
TL_LED5: R725.1 SW25.6
TL_MAX: L11.1 R50.1 R713.2
TL_MICBIASA1: U1.N6(MICBIAS)
TL_MICBIASA1 (page 005_AMIC): SW11.7
TL_MICBIASA2: SW10.7
TL_MICBIASB1: SW9.7
TL_MICBIASB2: SW8.7
TL_PA0: U1.B7(PA0)
TL_PA0 (page 004_Interface): J62.1
TL_PA1: U1.B6(PA1)
TL_PA1 (page 004_Interface): J62.3
TL_PA2: U1.A6(PA2)
TL_PA2 (page 004_Interface): J62.9
TL_PA3: U1.B5(PA3)
TL_PA3 (page 004_Interface): J3.6 R745.1
TL_PA4: U1.A5(PA4)
TL_PA4 (page 004_Interface): J3.10 R744.1
TL_PA5: U1.B4(PA5)
TL_PA5 (page 004_Interface): J3.8 SW23.1
TL_PA6: U1.B3(PA6)
TL_PA6 (page 004_Interface): J3.14 SW24.1
TL_PA7: U1.A4(PA7)
TL_PA7 (page 009_PWR): J70.4
TL_PB0: U1.E2(PB0)
TL_PB0 (page 004_Interface): J62.19
TL_PB1: U1.E1(PB1)
TL_PB1 (page 004_Interface): J4.6 SW20.1
TL_PB2: U1.D2(PB2)
TL_PB2 (page 004_Interface): J4.4 SW21.1
TL_PB3: U1.D1(PB3)
TL_PB3 (page 004_Interface): SW26.5
TL_PB4: U1.C2(PB4)
TL_PB4 (page 004_Interface): SW26.2
TL_PB5: U1.C1(PB5)
TL_PB5 (page 004_Interface): SW25.5
TL_PB5_EMMC: J62.7 SW25.4
TL_PB6: U1.B2(PB6)
TL_PB6 (page 004_Interface): J62.5 SW17.3
TL_PB7: U1.B1(PB7)
TL_PB7 (page 004_Interface): J62.17
TL_PC0: U1.A3(PC0)
TL_PC0 (page 004_Interface): J62.11
TL_PC1: U1.A2(PC1)
TL_PC1 (page 004_Interface): J62.13
TL_PC6: U1.A1(PC6)
TL_PC6 (page 004_Interface): J62.15
TL_PF0: U1.F1(PF0)
TL_PF0 (page 004_Interface): J58.1
TL_PF1: U1.F2(PF1)
TL_PF1 (page 004_Interface): J58.3
TL_PF2: U1.G1(PF2)
TL_PF2 (page 004_Interface): J58.5
TL_PF3: U1.H1(PF3)
TL_PF3 (page 004_Interface): J58.7
TL_PF4: U1.G2(PF4)
TL_PF4 (page 004_Interface): J62.21
TL_PF5: U1.H2(PF5)
TL_PF5 (page 004_Interface): J62.23
TL_PG0: C472.2 U1.F8(PG0)
TL_PG1: C472.1 U1.G8(PG1)
TL_PG2: C471.2 U1.K8(PG2)
TL_PG3: C471.1 U1.L8(PG3)
TL_PG4: C473.1 C475.2 TP5.1 U1.M8(PG4)
TL_PG5: C473.2 C474.1 TP7.1 U1.N8(PG5)
TL_PG6: U1.N7(PG6)
TL_PG6 (page 009_PWR): J70.5
TL_PI0: U1.E4(PI0)
TL_PI0 (page 005_AMIC): SW18.1 SW18.2
TL_PI0_P: C476.1 R718.1 SW18.10
TL_PI1: U1.F4(PI1)
TL_PI1 (page 005_AMIC): SW18.3 SW18.4
TL_PI1_N: C477.1 R718.2 SW18.11
TL_PI2: U1.G4(PI2)
TL_PI2 (page 004_Interface): J64.1
TL_PI3: U1.H6(PI3)
TL_PI3 (page 004_Interface): J64.5
TL_PI4: U1.J6(PI4)
TL_PI4 (page 004_Interface): J64.7 J64.11
TL_PI5: U1.K6(PI5)
TL_PI5 (page 004_Interface): J64.3 J64.9
TL_RST: C8.1 SW1.1 U1.C9(RST)
TL_SPK_LOUT: J57.8(L) R690.2
TL_SPK_ROUT: J57.3(R) R38.2
TL_TDI: J4.12 SW26.3
TL_TDO: J4.11 SW26.4
TL_VBAT: C12.1 J70.12 U1.K9(VBAT)
TL_VBAT_3V3: C92.1 C93.1 J70.8 U21.5(VOUT)
TL_VBAT_SIMO: C28.1 C113.1 J70.10 U1.H8(VBAT_SIMO)
TL_VBUS: C11.1 R45.2 U1.L9(VBUS)
TL_VDDAO: C25.1 C26.1 R739.1 U1.M2(VDDAO)
TL_VDDIO1: C4.1 J4.7 R36.1 R730.2 R731.2 U1.N9(VDDIO1)
TL_VDDIO4: C27.1 R732.2 R733.2 U1.P8(VDDIO4)
TL_VDDIO5: C10.1 R736.1 R741.2 U1.C8(VDDO5)
TL_VDDRF1: C6.1 R737.1 U1.D8(VDDRF1)
TL_VDDRF2: C5.1 R735.2 U1.E8(VDDRF2)
TL_VIN: C15.1 C19.1 D1.A(ANODE) D10.A(ANODE) J70.1 J70.7 J70.9 J70.11 R713.1 U54.1(VIN) U54.3(CE) U55.1(VIN) U55.3(CE)
TL_XTALM: C36.2 U1.A8(XTAL_M) Y2.1
TL_XTALP: C35.2 U1.A7(XTAL_P) Y2.3
N20536109: L5.2 R43.2
N20536111: L6.2 R44.2
N20574830: C48.1 R16.2 U6.4(VDD)
N20574981: C47.1 R19.2 U7.4(VDD)
N20575273: R17.1 SW11.13
N20575330: R18.1 SW10.13
N20575385: R11.1 SW9.13
N20575656: C40.1 R8.2 U3.4(VDD)
N20677576: C39.1 R10.2 U2.4(VDD)
N20677726: R9.1 SW8.13
N20851990: C72.1 R39.1 R668.2 U53.14(INL-)
N20851994: C72.2 R38.1 R39.2 U53.12(OUTL)
N20852024: C73.1 C460.1 C461.1 L11.2 U53.1(PVDD) U53.9(SVDD2) U53.13(SVDD)
N20852182: C462.2 R668.1
N20852188: C71.1 U53.11(BIAS)
N20852219: C463.2 R30.1
N20852229: R30.2 R31.2 U53.15(INL+)
N20852235: C70.1 U53.2(C1P)
N20852237: C70.2 U53.4(C1N)
N20852263: R687.2 R688.2 U53.7(INR+)
N20852308: C464.2 R688.1
N20852314: C69.1 U53.5(PVSS)
N20852351: C465.2 R689.1
N20852353: C467.1 R689.2 R692.1 U53.8(INR-)
N20852359: C467.2 R690.1 R692.2 U53.10(OUTR)
N20852392: C466.1 R50.2 R712.1 SP5.1 U53.16(\\~{SHDN})
N20909763: R715.2 R717.1 U54.4(FB)
N20909880: R721.2 R723.1 U55.4(FB)
N20909918: R723.2 R724.1
N20915858: C431.1 C432.1 U56.C2(VDDI)
N20915988: R666.2 U56.M6(CLK)
N20942233: R736.2 R737.2 R738.2 R739.2 R740.2
N20953978: J22.2(D-) R53.1
N20953991: J22.3(D+) R55.1
N20954081: J21.2(D-) R47.1
N20954094: J21.3(D+) R48.1
N20958641: L3.1 U1.H9(IND2_SIMO)
N20958643: L3.2 U1.J9(IND1_SIMO)
N20958733: C16.1 C17.1 U1.J2(VCAP)
N20958777: C13.1 U1.L2(VREG_DAC)
N20959069: C24.1 U1.N4(VREG)
N20968251: D8.A(ANODE) R727.2
N20968303: D9.A(ANODE) R728.2
N20971815: D10.C(CATHODE) R729.1
N20971817: Q3.3(D) R729.2
N20971901: D1.C(CATHODE) R5.1
N20971903: Q2.3(D) R5.2
N20984994: R35.2 SW17.1
N20985013: R36.2 SW17.4
N20986499: D6.A(ANODE) R725.2
N21011857: D11.A(ANODE) R744.2
N21011984: D12.A(ANODE) R745.2

Not connected (* = marked no-connect by the designer): J3 1* 4* 12*; J4 1* 2* 10*; J57 1(M)* 4* 5* 7*; J70 3*; SW14 1* 4* 5* 8*; SW15 1* 4* 5* 8*; SW17 2* 5* 6* 7* 8*; SW18 5*; SW25 1* 2* 3*; U4 1* 4*; U5 1* 4*; U8 1* 4*; U9 1* 4*; U17 1* 4*; U18 1* 4*; U21 4(NC)*; U56 A1(NC) A2(NC1) A7(RFU) A8(NC2) A9(NC3) A10(NC4) A11(NC5) A12(NC6) A13(NC7) A14(NC8) B1(NC9) B7(NC10) B8(NC11) B9(NC12) B10(NC13) B11(NC14) B12(NC15) B13(NC16) B14(NC17) C1(NC18) C3(NC19) C5(NC20) C7(NC39) C8(NC38) C9(NC37) C10(NC36) C11(NC35) C12(NC34) C13(NC33) C14(NC32) D1(NC31) D2(NC30) D3(NC29) D4(RFU2) D12(NC28) D13(NC27) D14(NC26) E1(NC25) E2(NC24) E3(NC23) E5(RFU1) E8(VSF7) E9(VSF6) E10(VSF5) E12(NC22) E13(NC21) E14(NC40) F1(NC41) F2(NC42) F3(NC43) F10(VSF4) F12(NC44) F13(NC45) F14(NC46) G1(NC47) G2(NC48) G3(RFU3) G10(VSF3) G12(NC49) G13(NC50) G14(NC51) H1(NC52) H2(NC53) H3(NC54) H12(NC55) H13(NC56) H14(NC57) J1(NC58) J2(NC59) J3(NC60) J12(NC75) J13(NC74) J14(NC73) K1(NC72) K2(NC71) K3(NC70) K6(RFU4) K7(RFU5) K10(VSF2) K12(NC69) K13(NC68) K14(NC67) L1(NC66) L2(NC65) L3(NC64) L12(NC63) L13(NC62) L14(NC61) M1(NC76) M2(NC77) M3(NC78) M7(NC79) M8(NC80) M9(NC81) M10(NC82) M11(NC83) M12(NC84) M13(NC85) M14(NC86) N1(NC87) N3(NC88) N6(NC89) N7(NC90) N8(NC91) N9(NC92) N10(NC93) N11(NC94) N12(NC95) N13(NC96) N14(NC97) P1(NC98) P2(NC99) P7(NC100) P8(NC101) P9(NC102) P10(VSF1) P11(NC103) P12(NC104) P13(NC105) P14(NC106)

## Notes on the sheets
sheet 1
- IO SUPPLY
- 1.7V~1.95V
- 2.7V~3.6V
- PWR SUPPLY
- 2.7V~3.6V
sheet 2
- Author
- Approved by
- Xiang
- Xiang
- Date
- Note
- REV1.0
- 2025/02/10
- Initial Version
- REV1.1
- 2025/03/04
- 1. IOVDD5 connected to LDO1V8
- REV1.2
- 2025/06/19
- Add VAD part
sheet 3
- VIN
- USB PORT
  USB 5V
- EMMC
- USB 5V
- Burning
  SWS
- 48M
  CL:6pF
- Debug USB
- RF
- H26M88002AMR
- EXT 3.3V
- Li-Battery
- 5 LEDs
- TL7519H
- LDO 3.3V
- VABT
- SIMO VBAT
- 4 Buttons
- SIMO-BK1-1.8V
- VDDRF1
- AVDD2
- SIMO-BK2-1.04V
- AVDD1
- VDDRF2
- SIMO-BK3-0.8V
- DVDD1+DVDD2
- LDO 3.3V
- LDO 1.8V
- JTAG-D25
- Differential
- JTAG-DSP
- AO1
- 3.55mm-Jack
  Single-end
- MAX97220A
- Differential
- AO2
- 3.55mm-Jack*2
- AMIC*4
- DMIC*4
- DMIC0
- DMIC1
- DMIC2
sheet 4
- Crystal
- VDDIO5
- VDDIO1
- 1.8V because of flash
- VDDIO1
- BK1: 1.8V
- BK2: 1.04V
- BK3: 0.8V
- GPIO 38
- 3.3V power domain
- VDDIO4
- 这4个IO是考虑给触摸按键使用的，实际使用就是如此
- 如果要测试IO功能，就直接这里焊接线就好了
sheet 5
- JTAG-DSP
- JTAG-D25
- CAD: keep the postion
- CAD: keep the postion
- UP-LOW(Default): 4-Wire JTAG Mode
- MIDDLE: NC
- DOWN-HIGH: 2-Wire JTAG Mode
sheet 6
- AMC4
- AMIC1
- AMC2
- AMC3
- S-E LINE IN
- DIF-LINE IN
- 1
- 9
- 1
- 9
- 2
- 10
- 2
- 10
- 3
- 11
- 3
- 11
- 4
- 5
- 12
- 13
- 4
- 5
- 12
- 13
- 1.8V LDO
- 6
- 14
- 6
- 14
- 1.8V LDO
- 7
- 15
- 7
- 15
- 3.3V LDO
- 8
- 16
- 8
- 16
- AMIC
- EX-S-E MIC IN
- 1
- 2
- 10
- 9
- 1
- 2
- 10
- 9
- 3
- 11
- 3
- 11
- 4
- 12
- 4
- 12
- 5
- 13
- 5
- 13
- 6
- 14
- 6
- 14
- 7
- 8
- 15
- 16
- 7
- 8
- 15
- 16
sheet 7
- 1.6V~3.6V
- 1.6V~3.6V
- 1.6V~3.6V
- 1.6V~3.6V
sheet 8
- POWER SUPPLY: 2.5V~5.5V
sheet 9
- Debug USB
- BK1: 1.8V
- PWR USB
- BK2: 1.04V
- 300mA
- OUTPUT: 2.1V/2.5V/3.3V
- Vout=0.6V*(1+R1/R2)
- 300mA
- OUTPUT: 1.5V/1.8V/2.8V
- Vout=0.6V*(1+R1/R2)
